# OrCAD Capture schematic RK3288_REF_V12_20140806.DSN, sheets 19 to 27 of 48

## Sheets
19 35.RAM-LPDDR2(220P) (option): size A3; title: RAM-LPDDR2(220P) (option); note: DDR-LPDDR2(220P) (option)
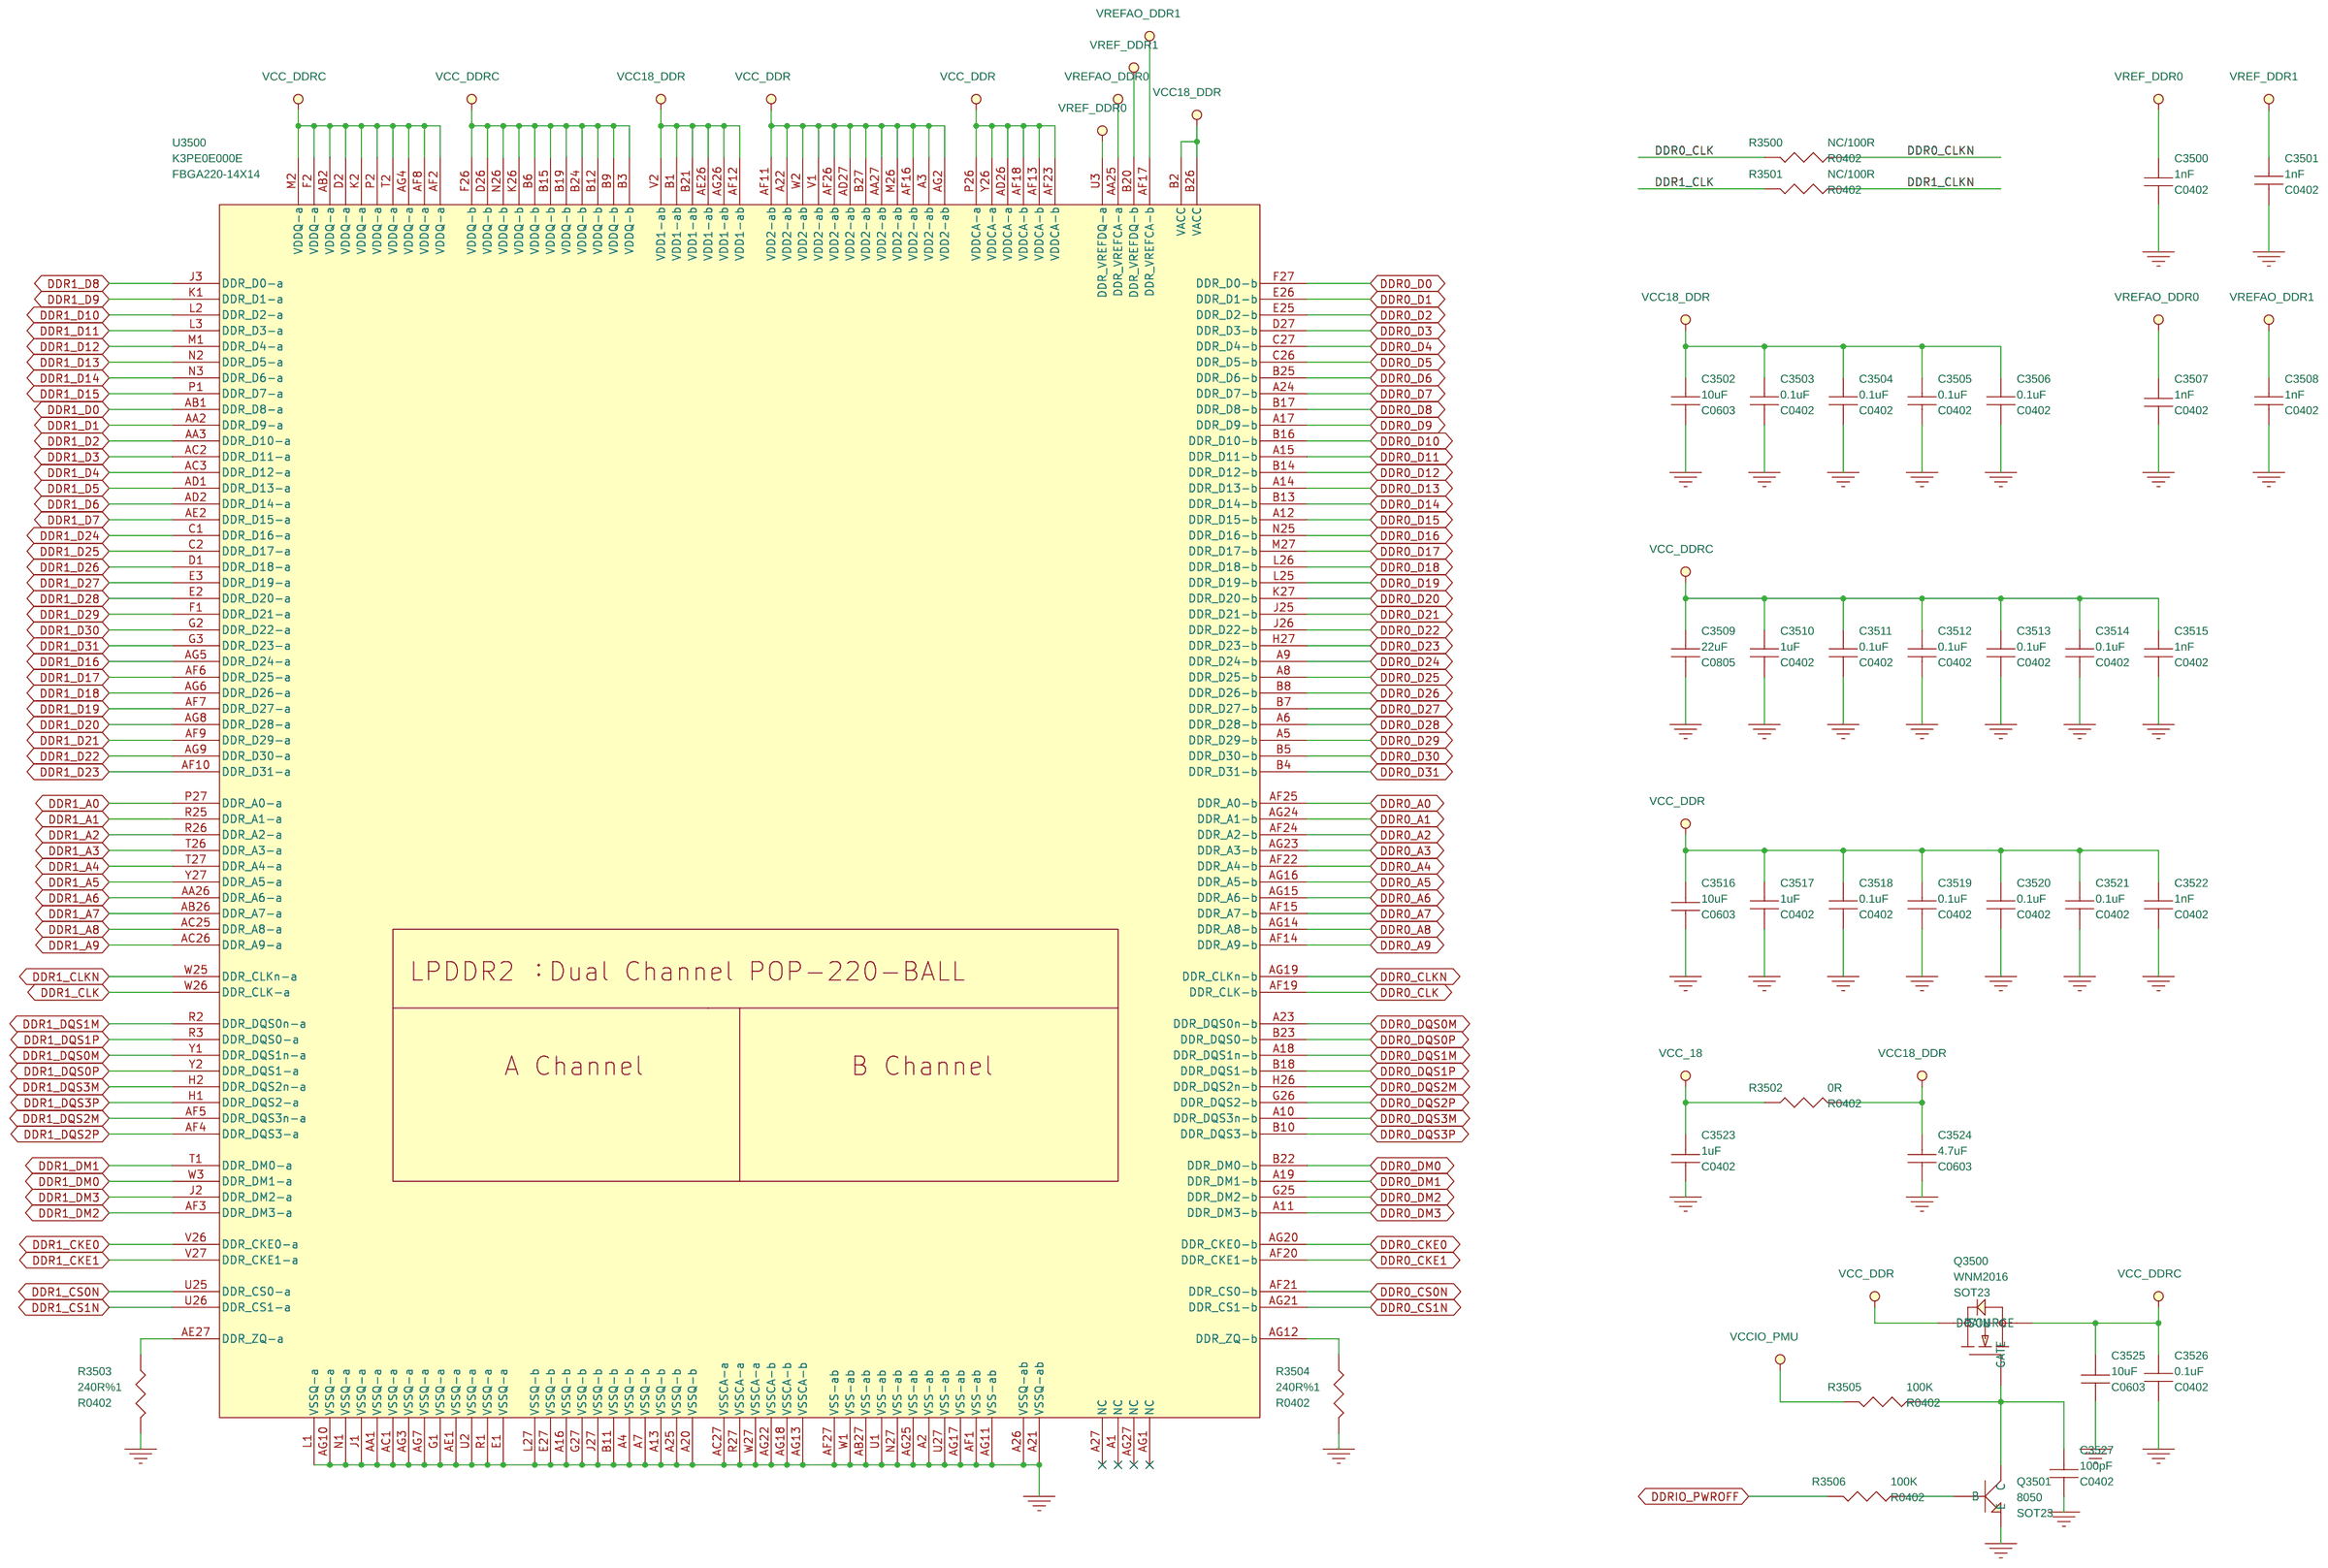
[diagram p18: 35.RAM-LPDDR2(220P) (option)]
20 36.RAM-LPDDR3(178P) (option): size Custom; title: RAM-LPDDR3(178P) (option); note: DDR-LPDDR3(178P) (option)
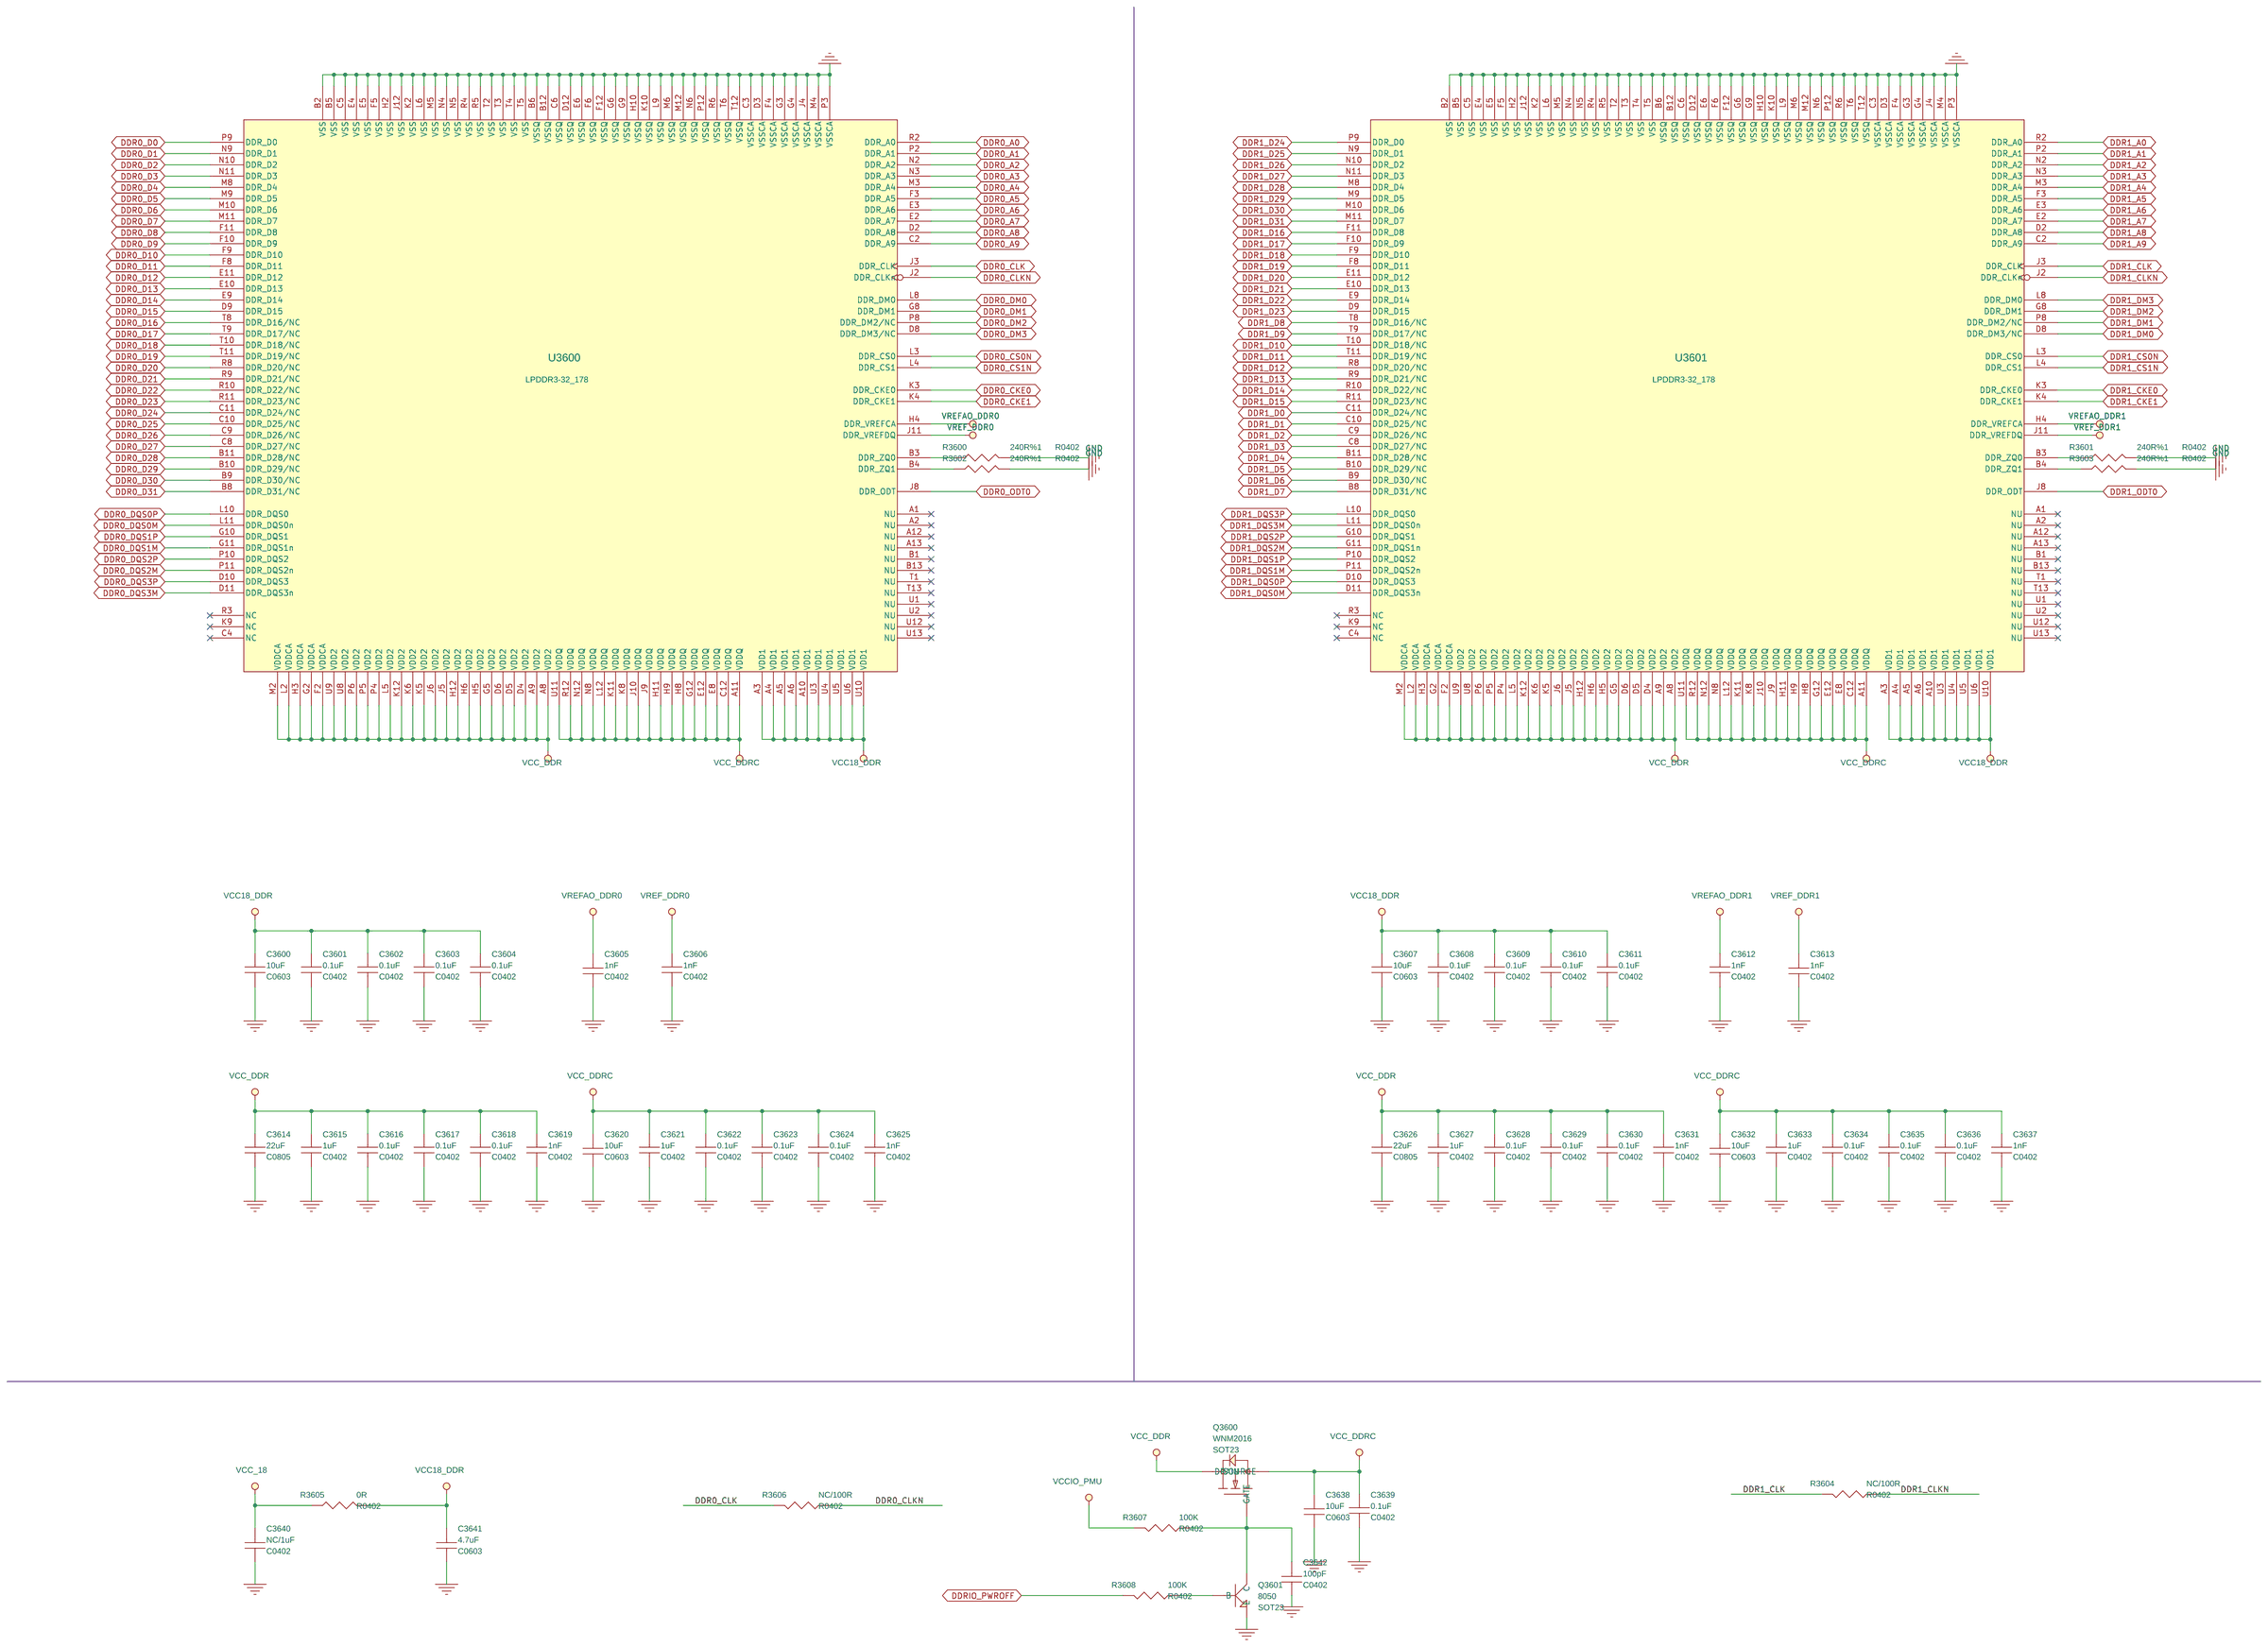
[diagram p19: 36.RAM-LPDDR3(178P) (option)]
21 40.Memory-eMMC: size A4; title: Flash-eMMC; note: Flash-eMMC
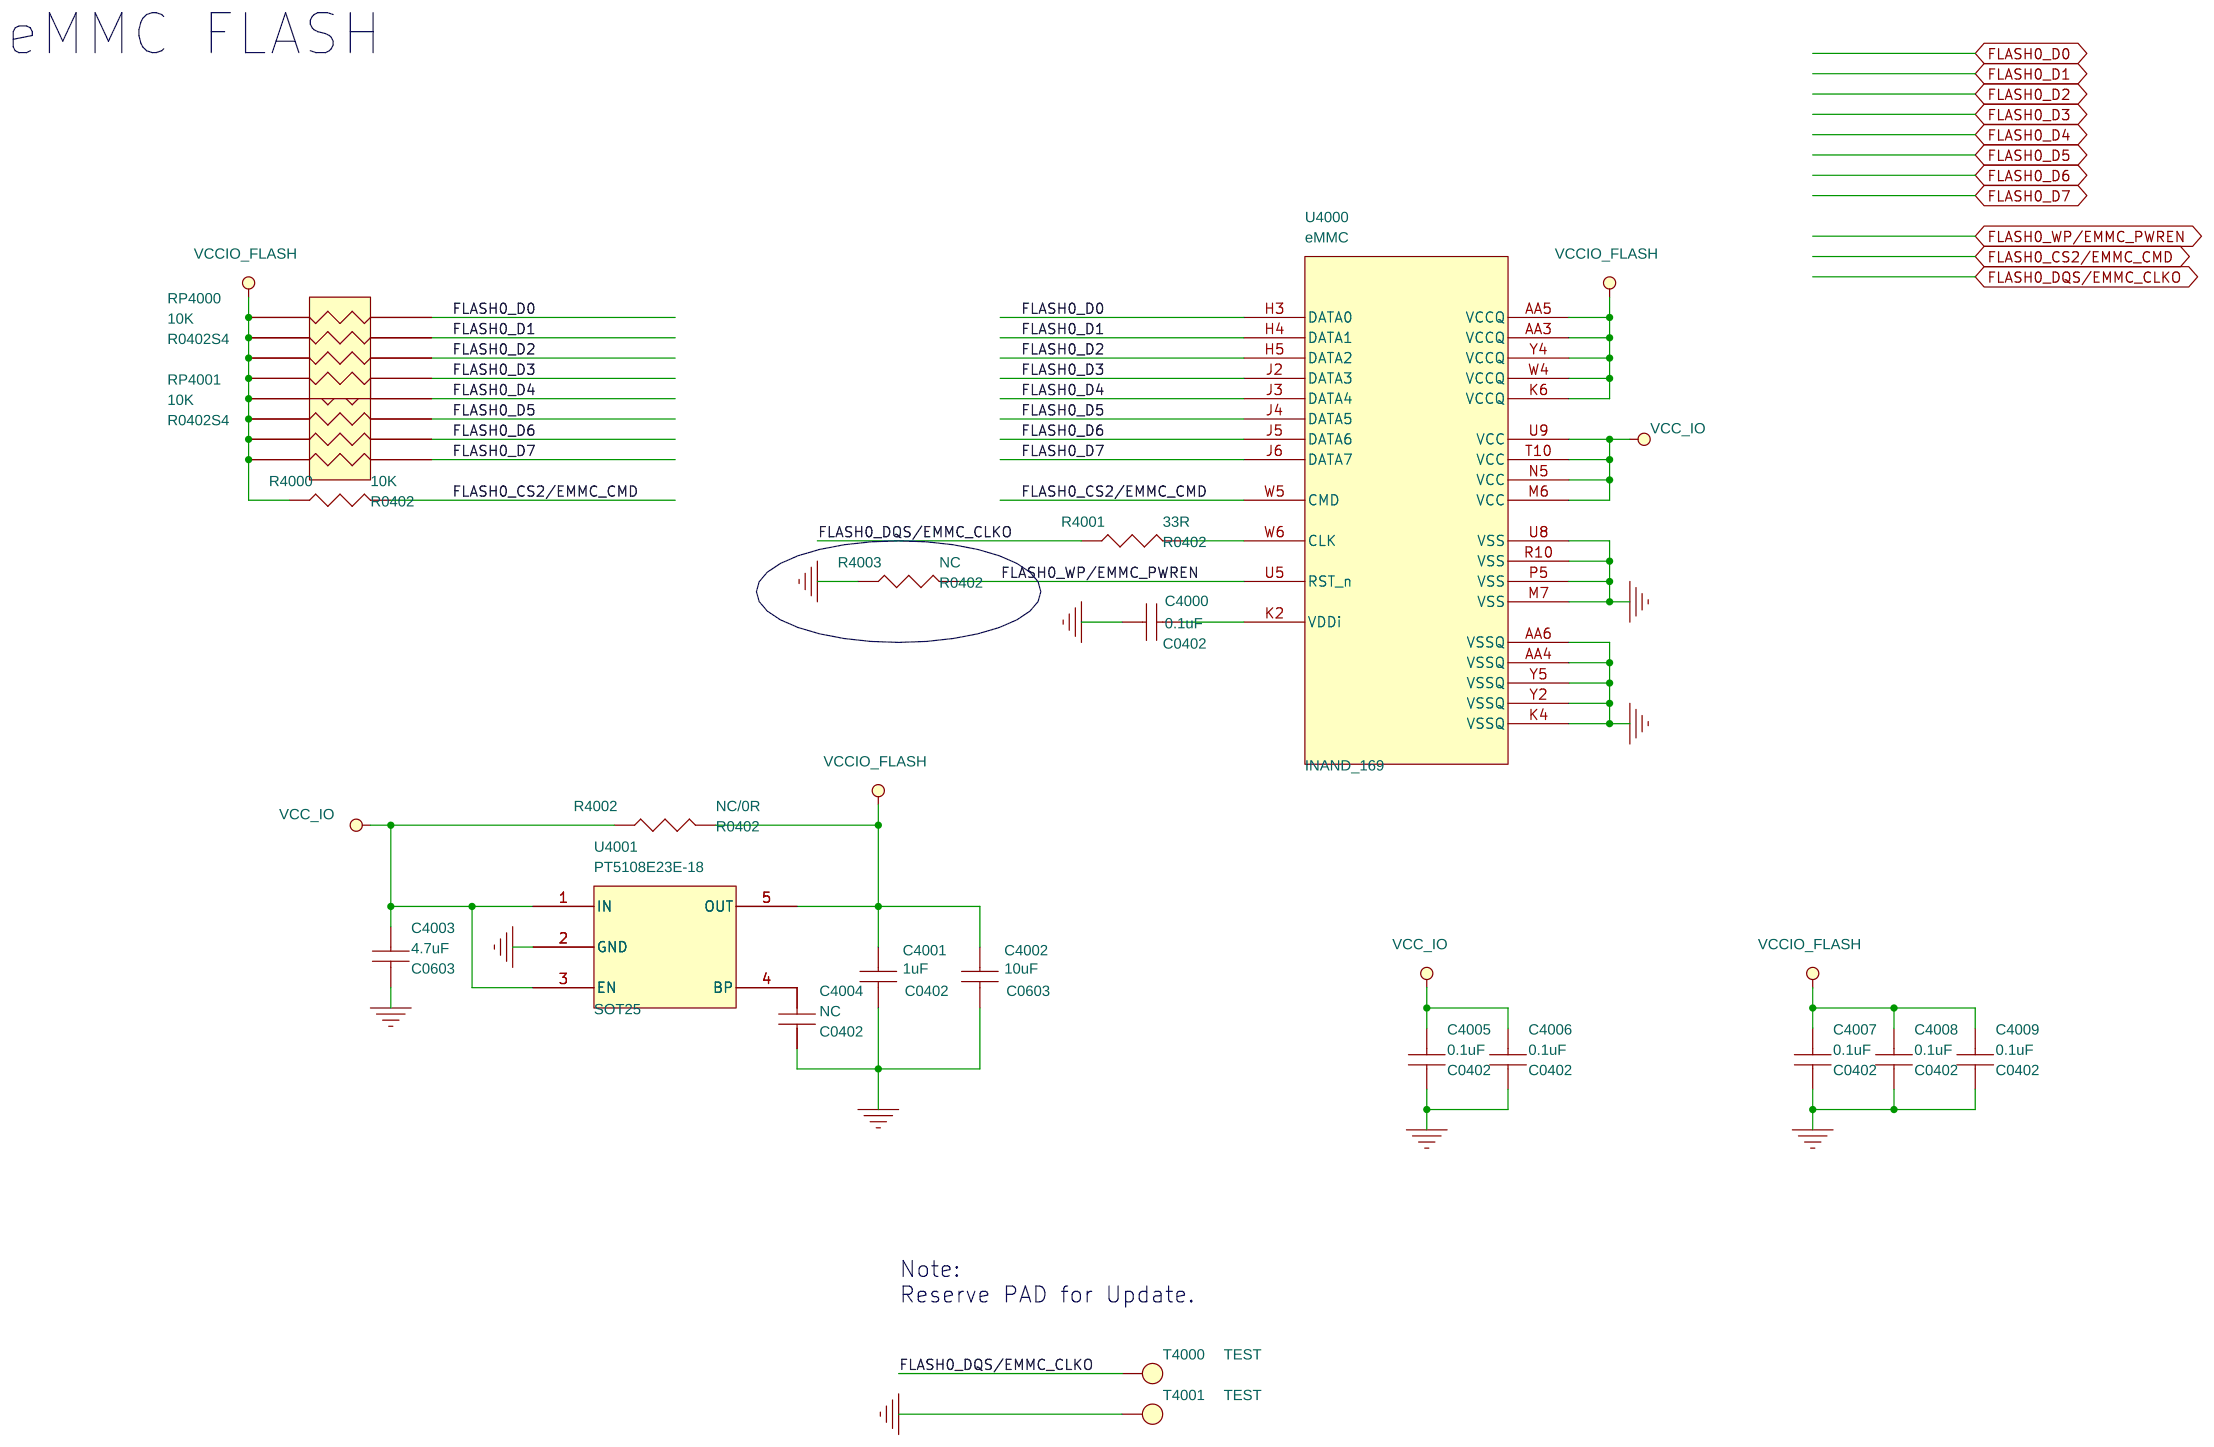
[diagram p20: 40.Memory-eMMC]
22 41.Memory-Nand FLASH (option): size A4; title: Flash-Nand FLASH (option); note: Flash-Nand FLASH (option)
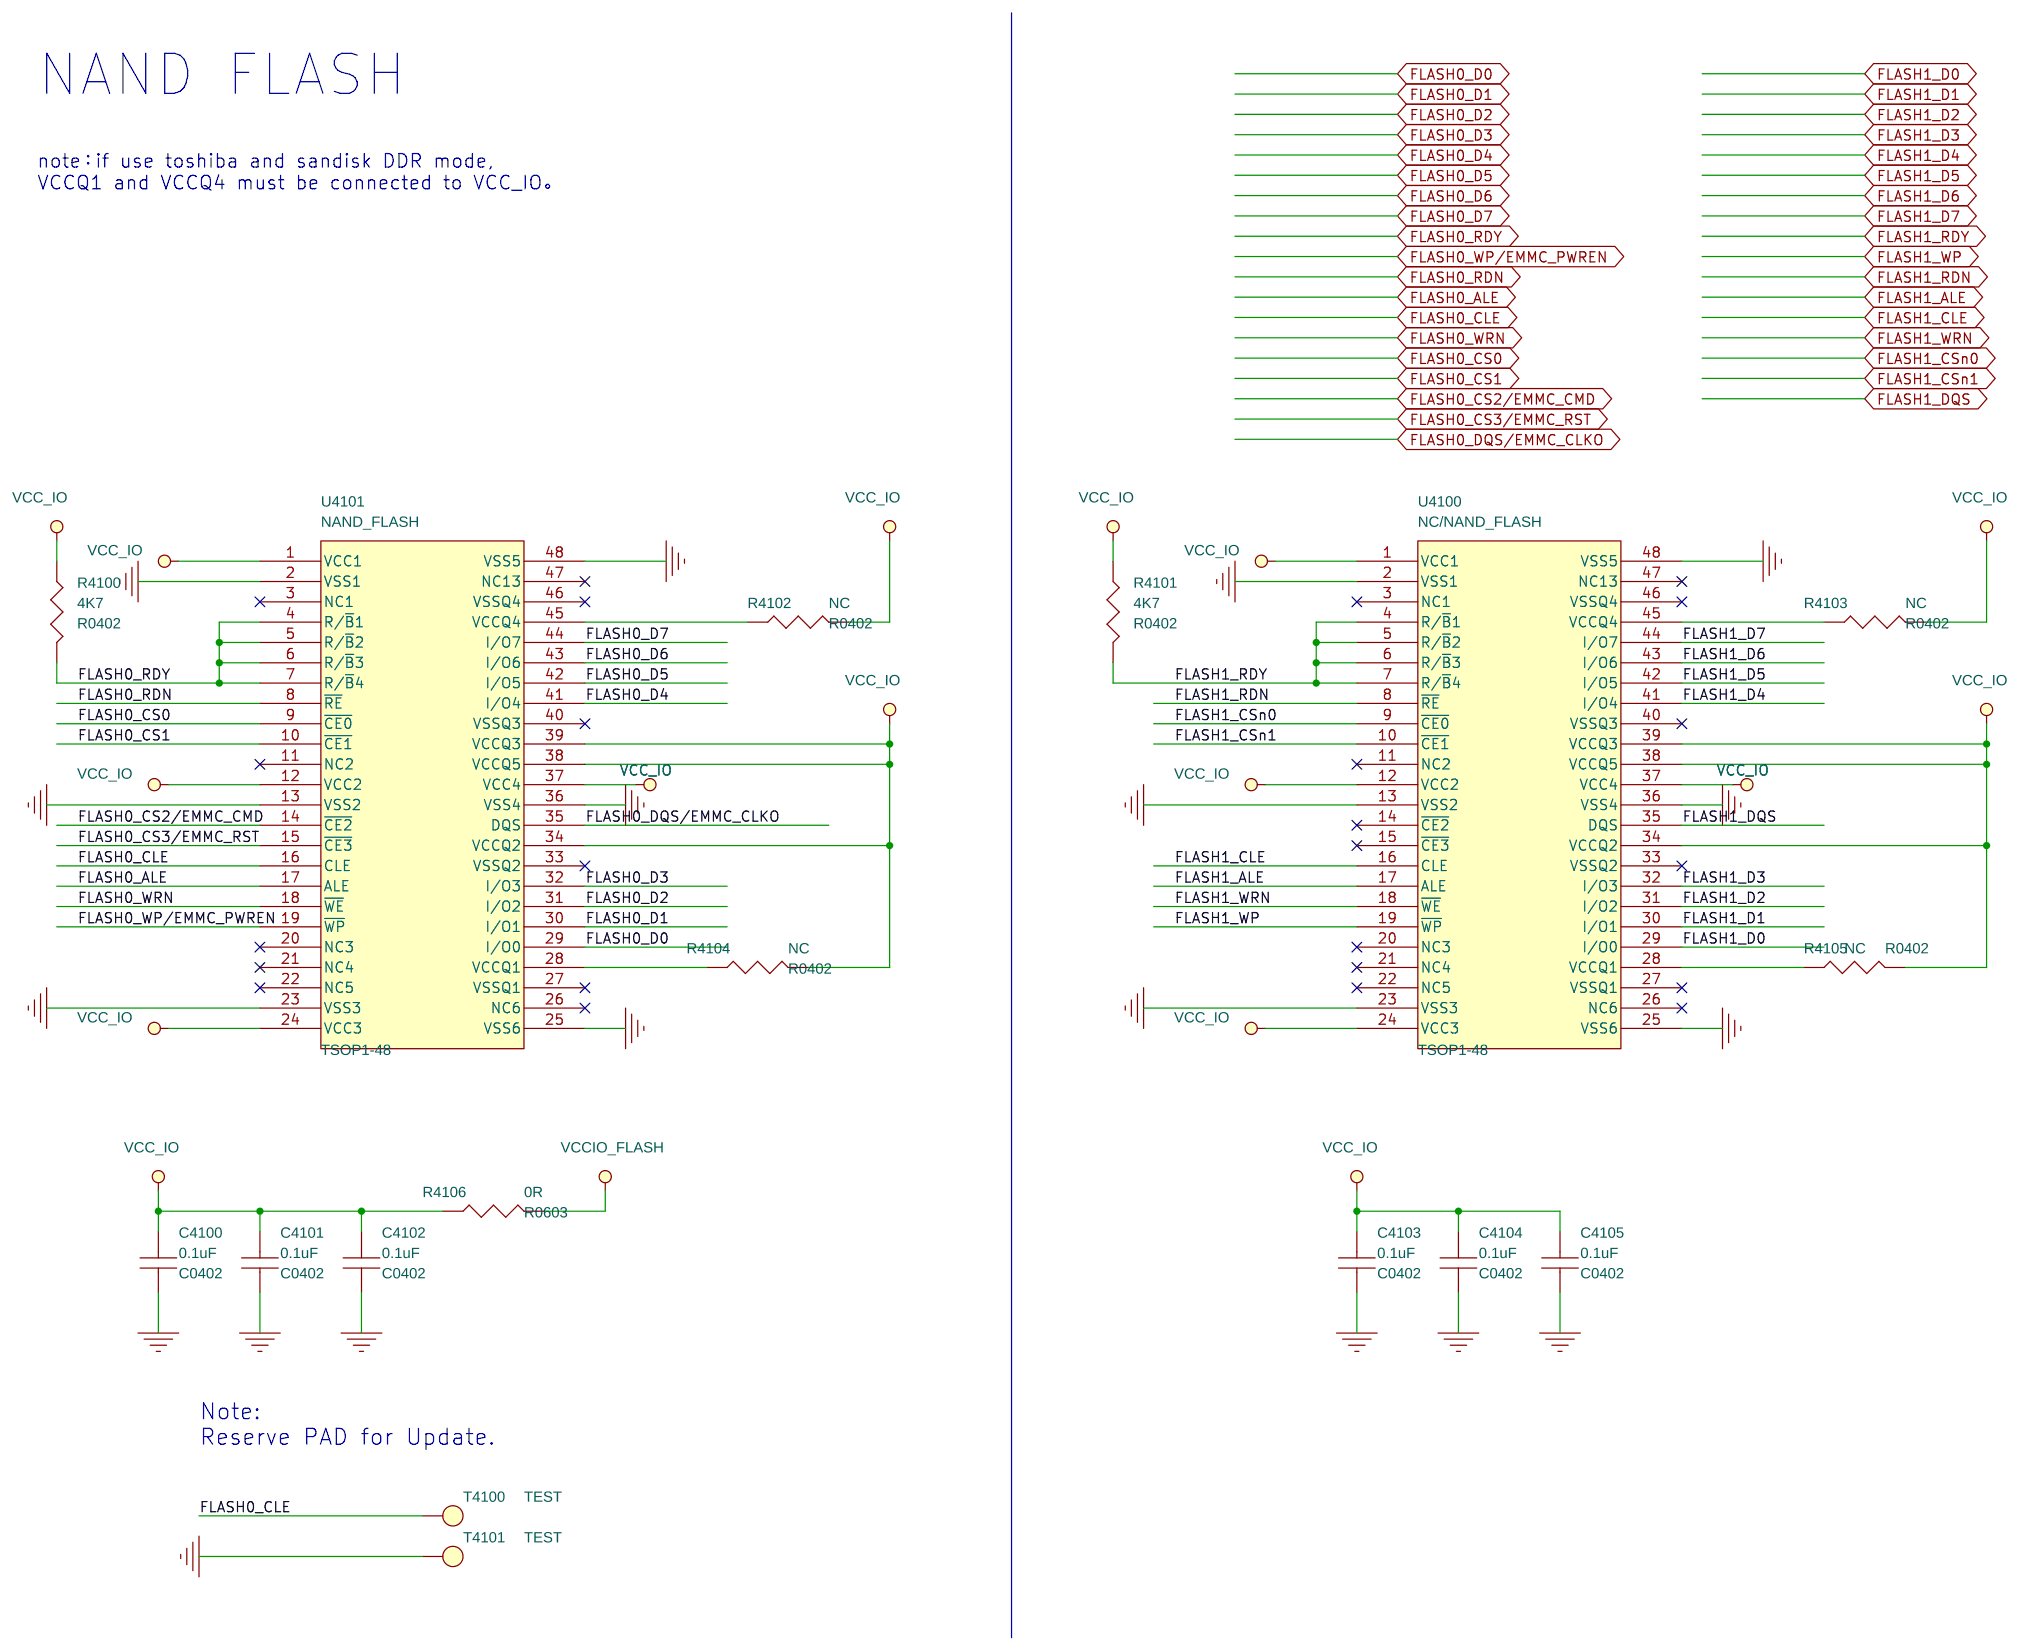
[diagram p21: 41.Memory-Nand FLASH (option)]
23 42.Memory-tSD (option): size A4; title: Flash-tSD (option); note: Flash-tSD (option)
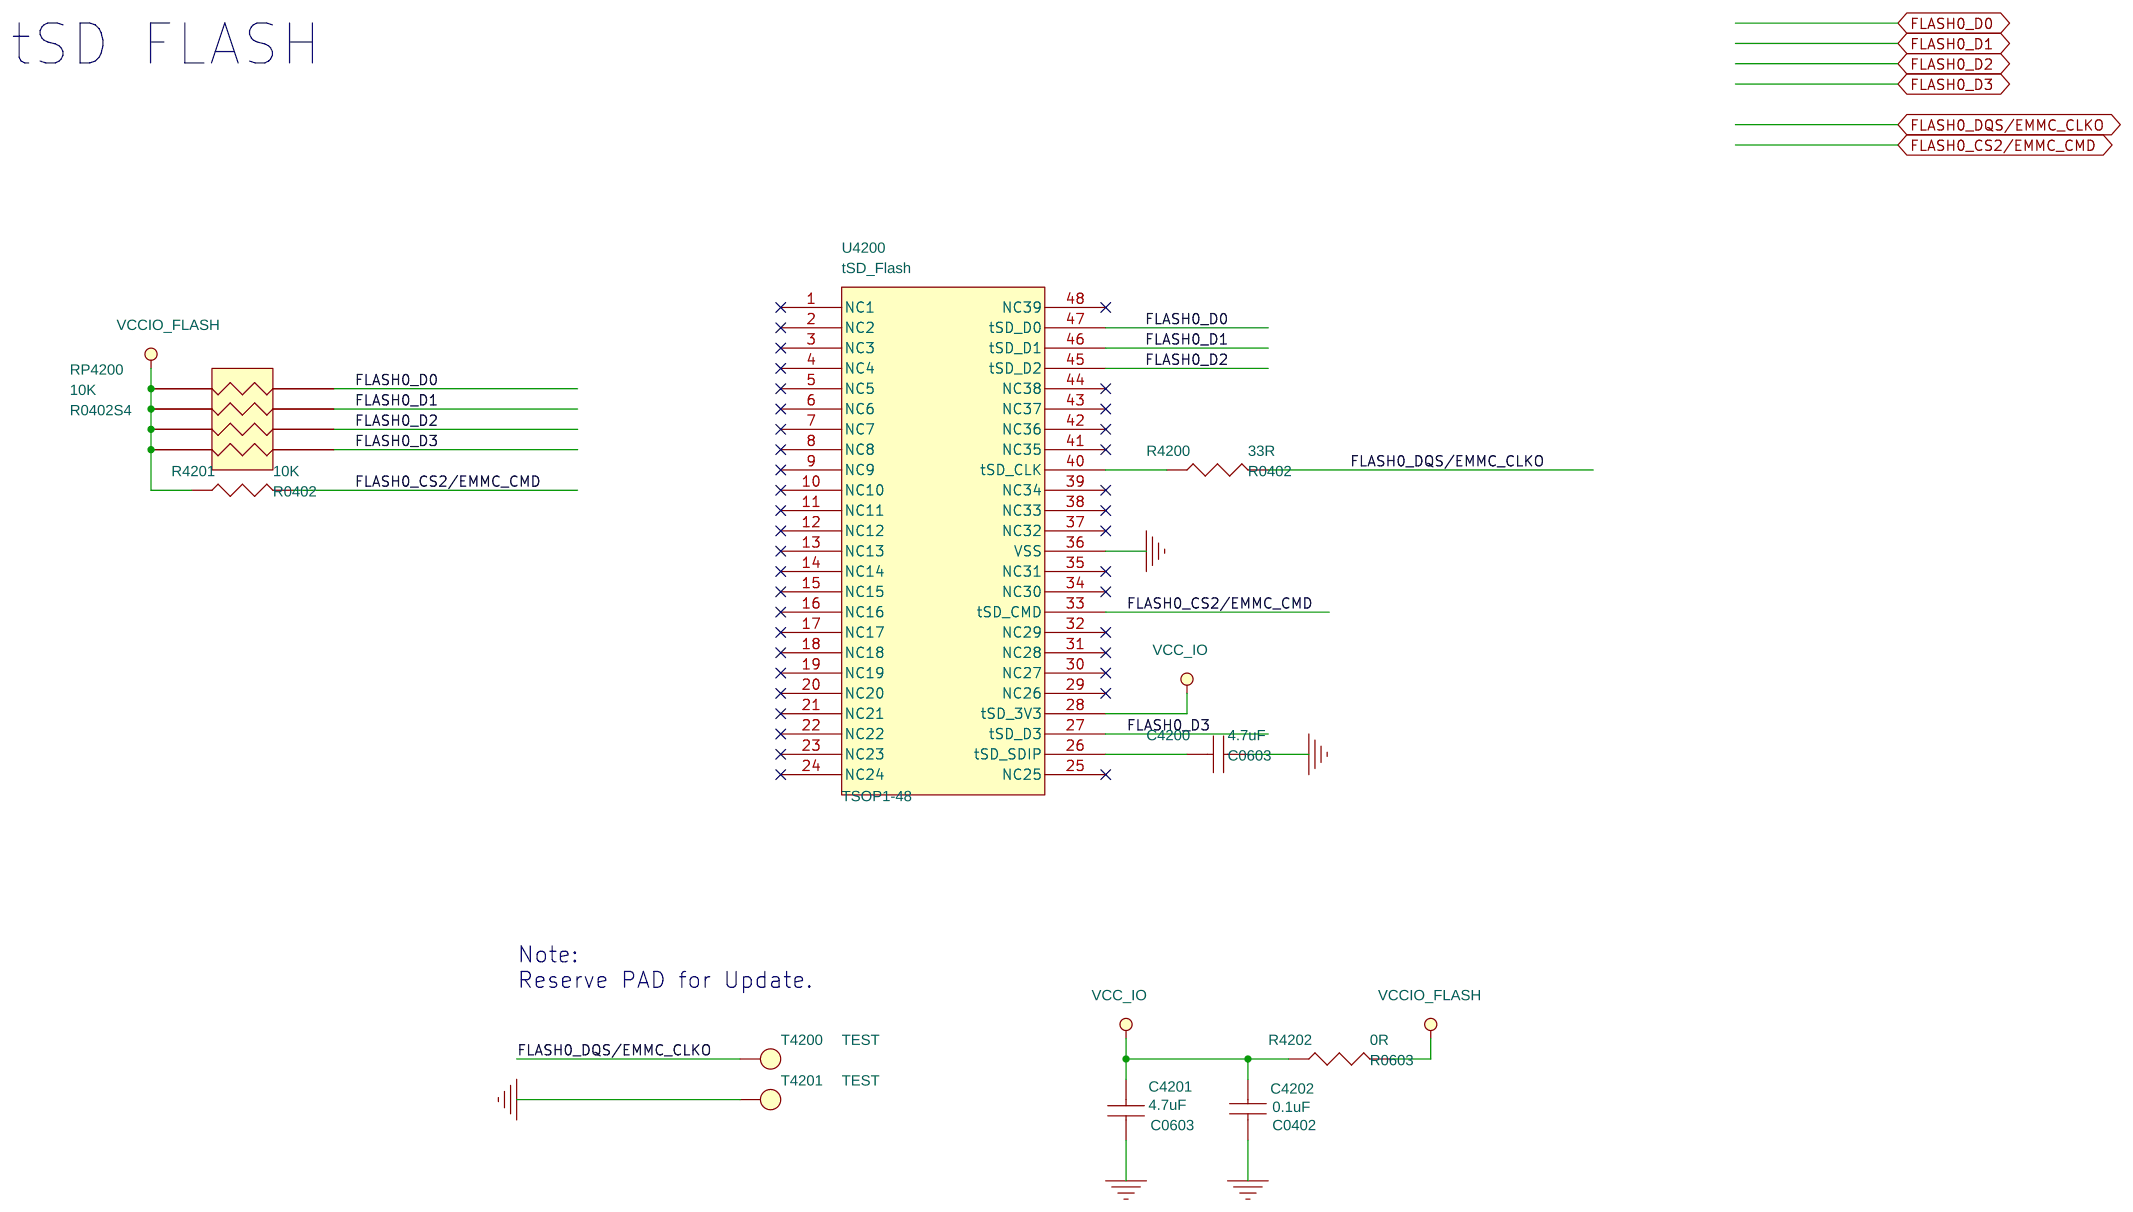
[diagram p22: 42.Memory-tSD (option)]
24 45.DVP power and Flash LED: size A3; title: DVP power and Flash LED; note: DVP power and Flash LED
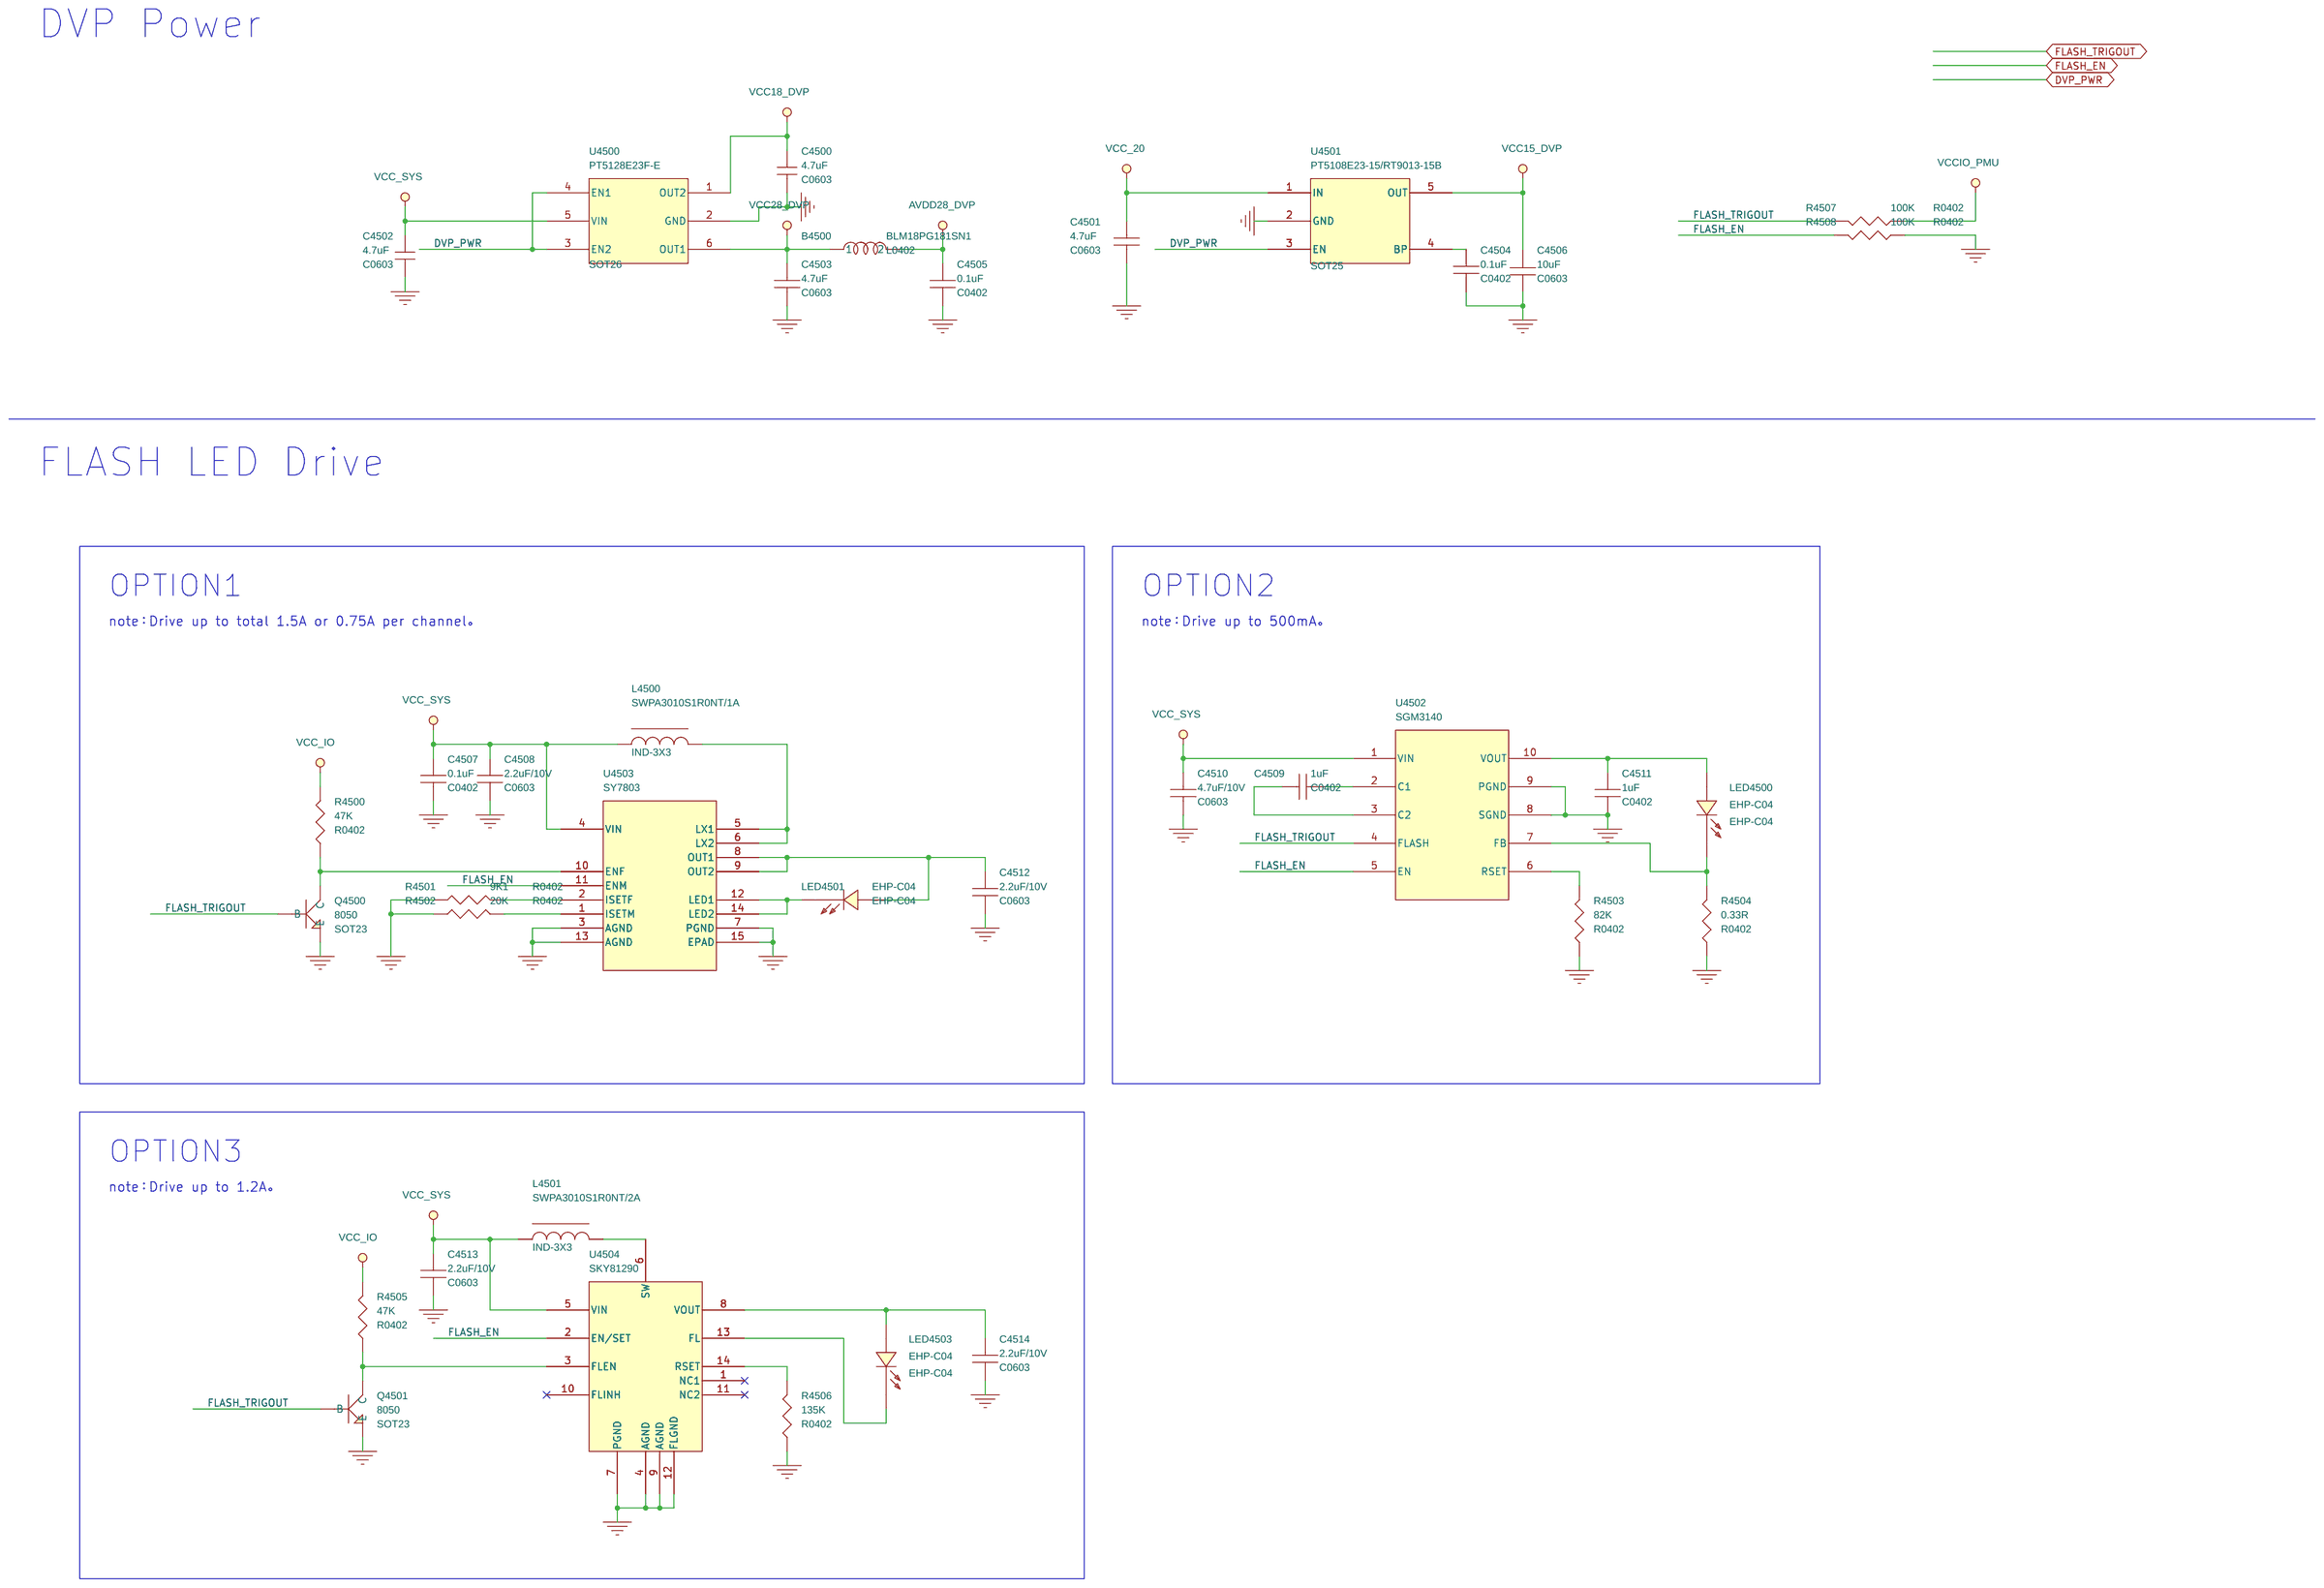
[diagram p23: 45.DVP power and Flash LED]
25 46.Camera-MIPI CSI: size A4; title: Camera-MIPI CSI; note: Camera-MIPI CSI
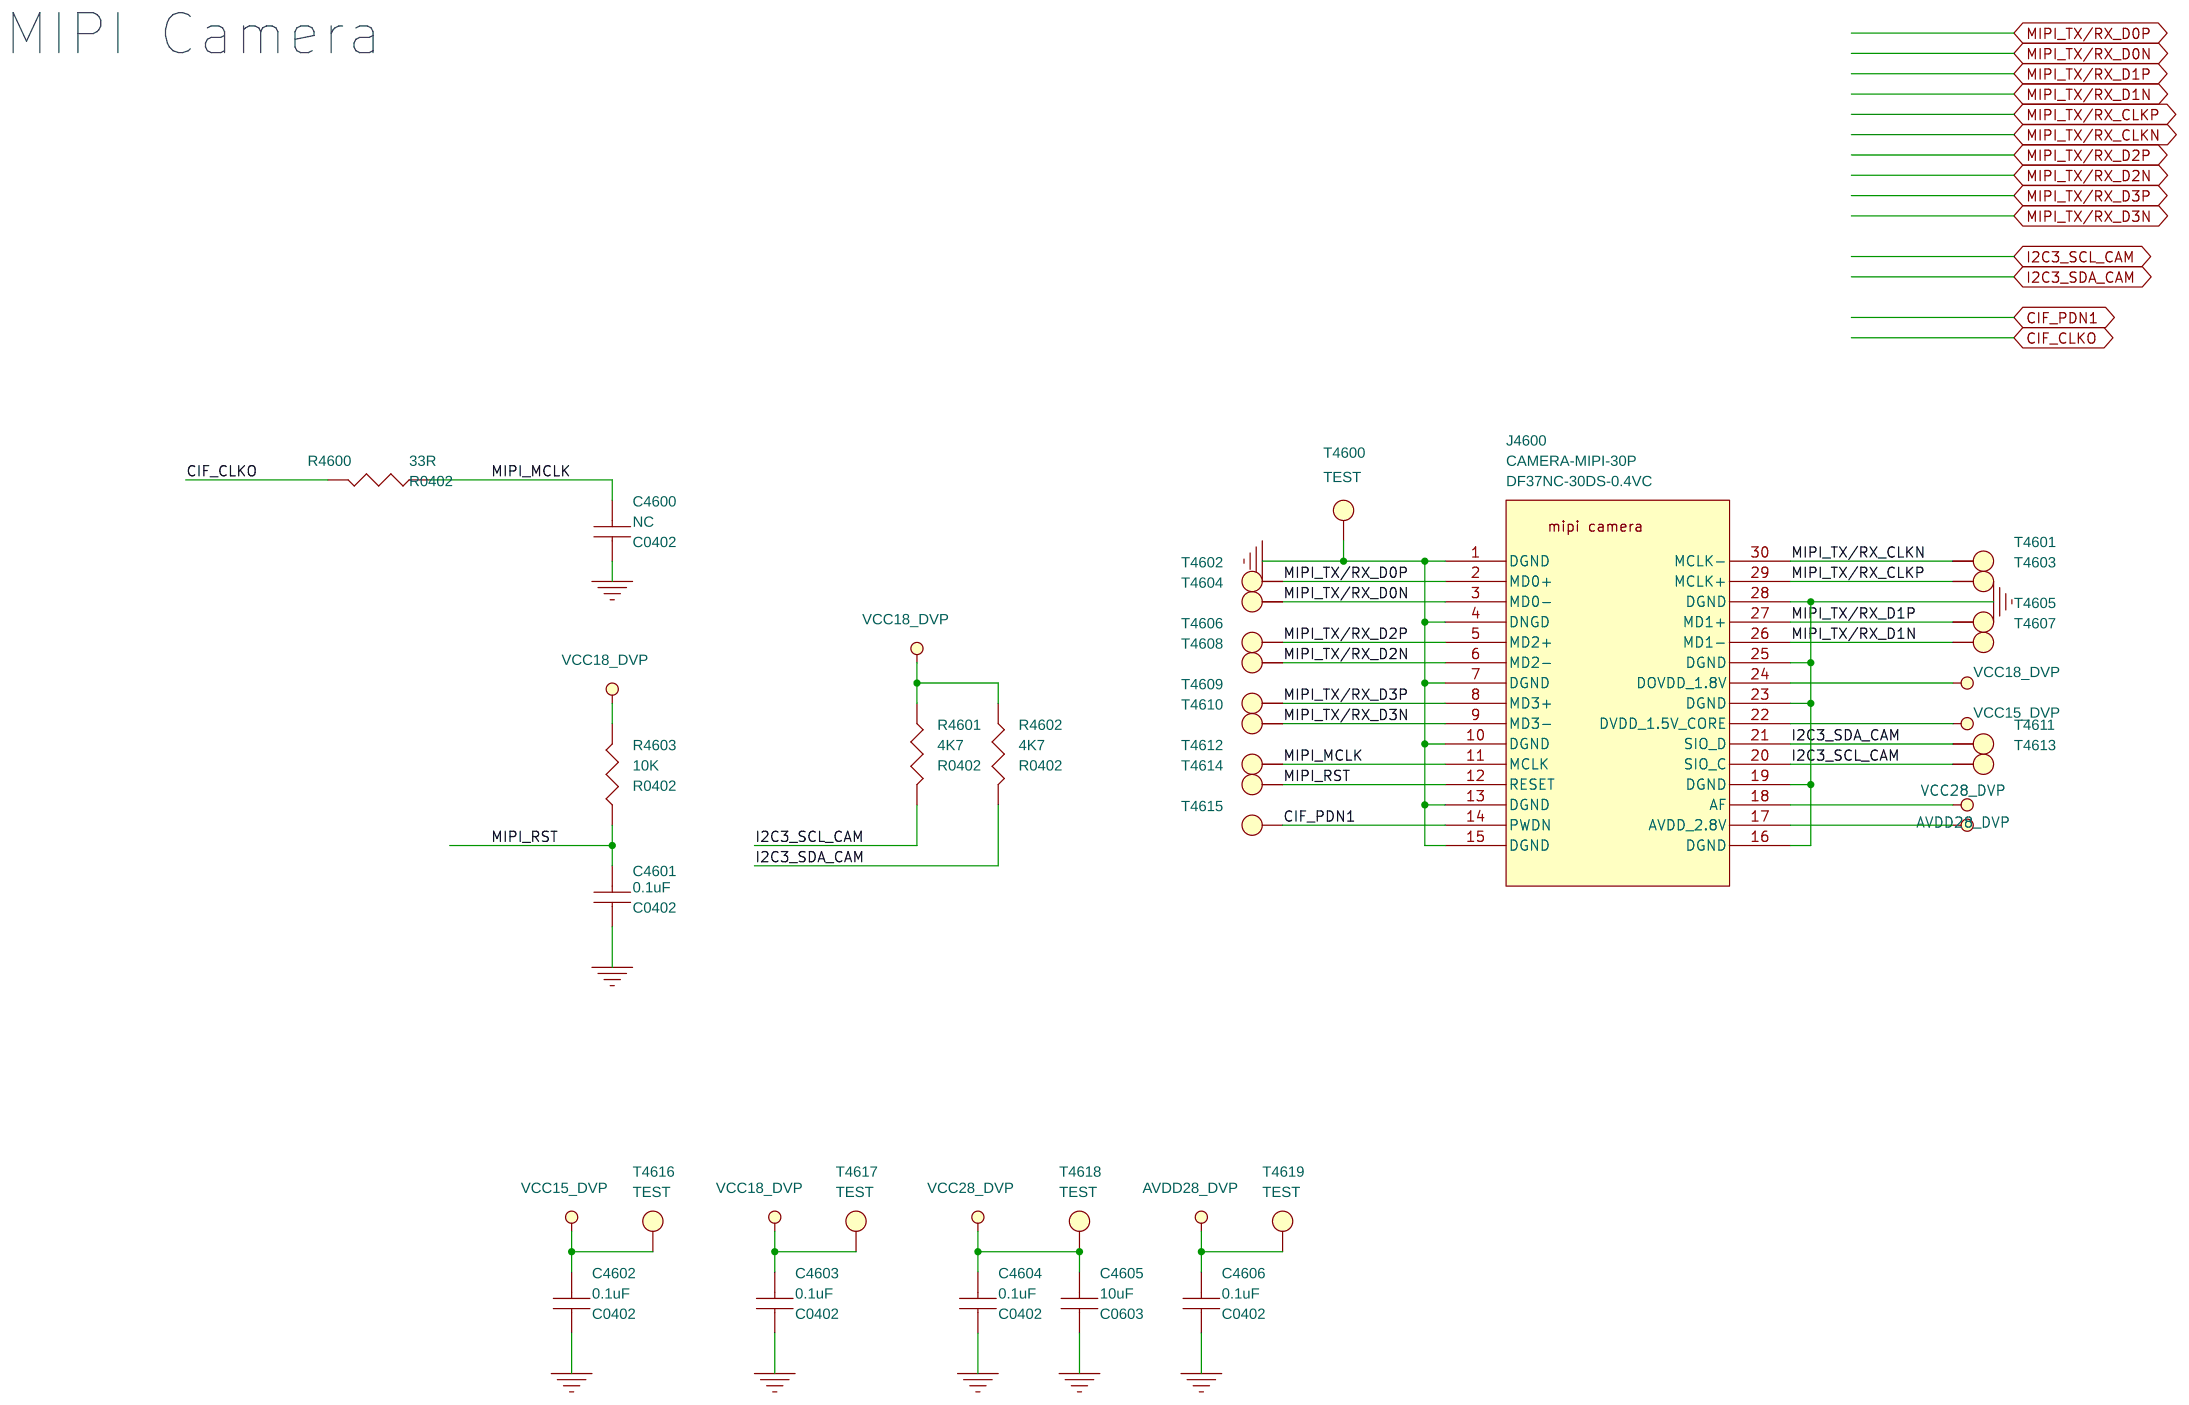
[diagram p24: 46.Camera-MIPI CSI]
26 47.Camera-CIF (option): size A4; title: Camera-CIF (option); note: Camera-CIF (option)
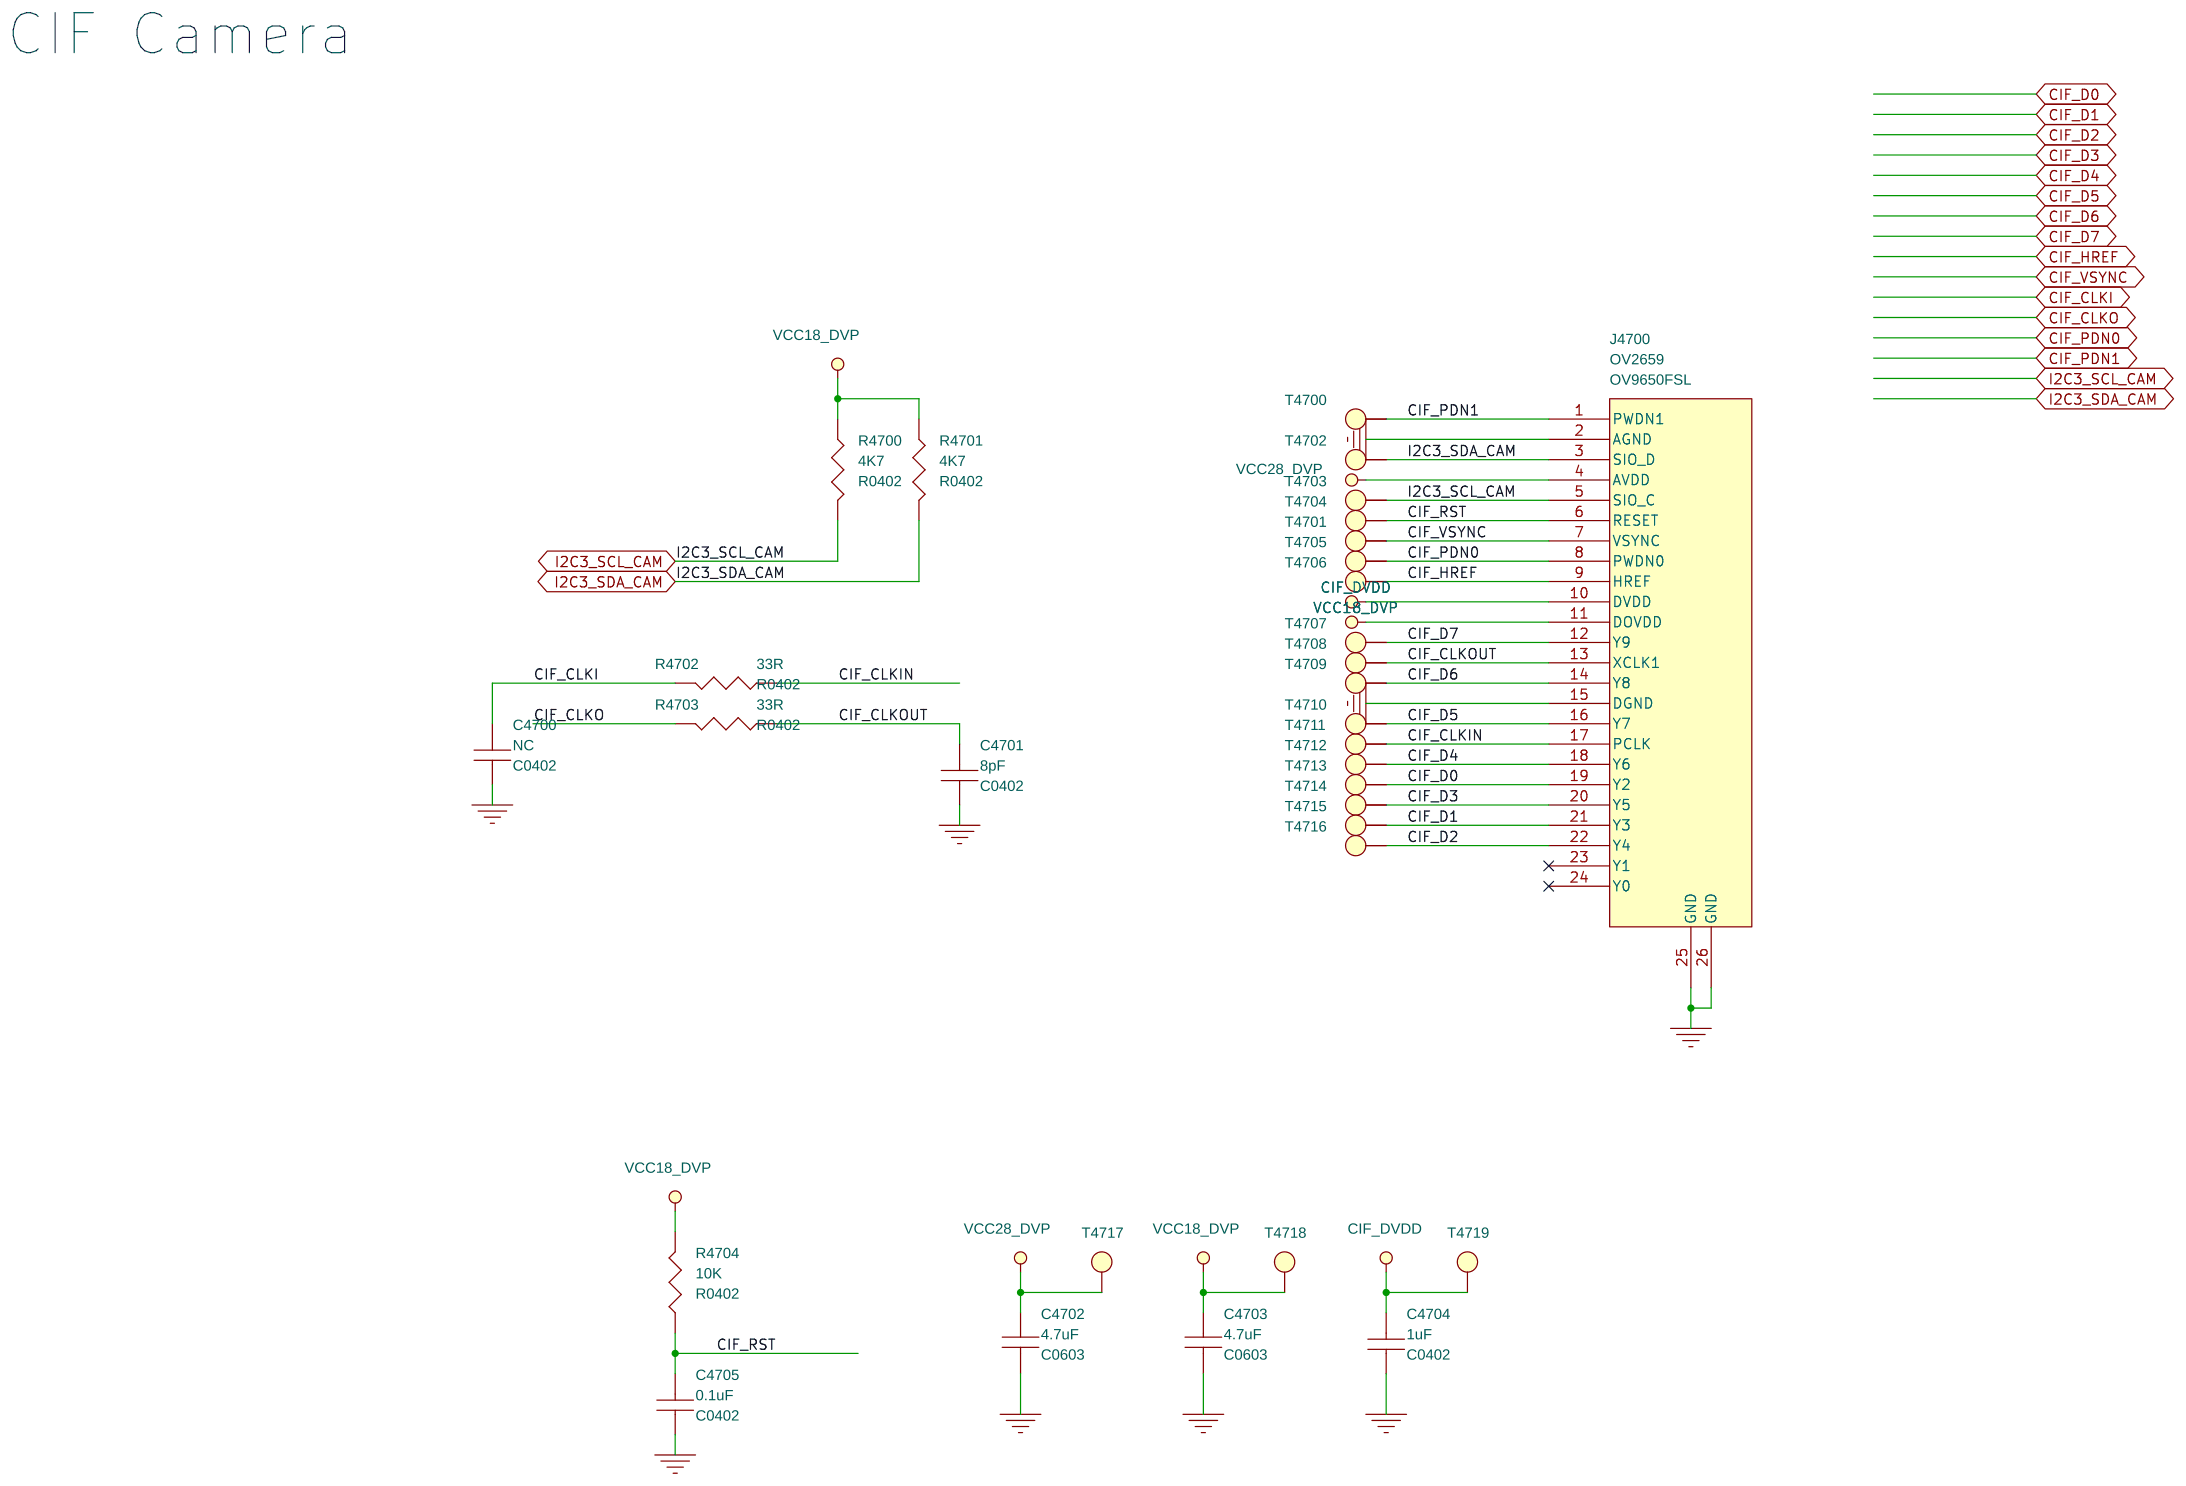
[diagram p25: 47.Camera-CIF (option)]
27 50.LCM-eDP Panel: size A4; title: LCM-eDP Panel; note: LCM-eDP Panel
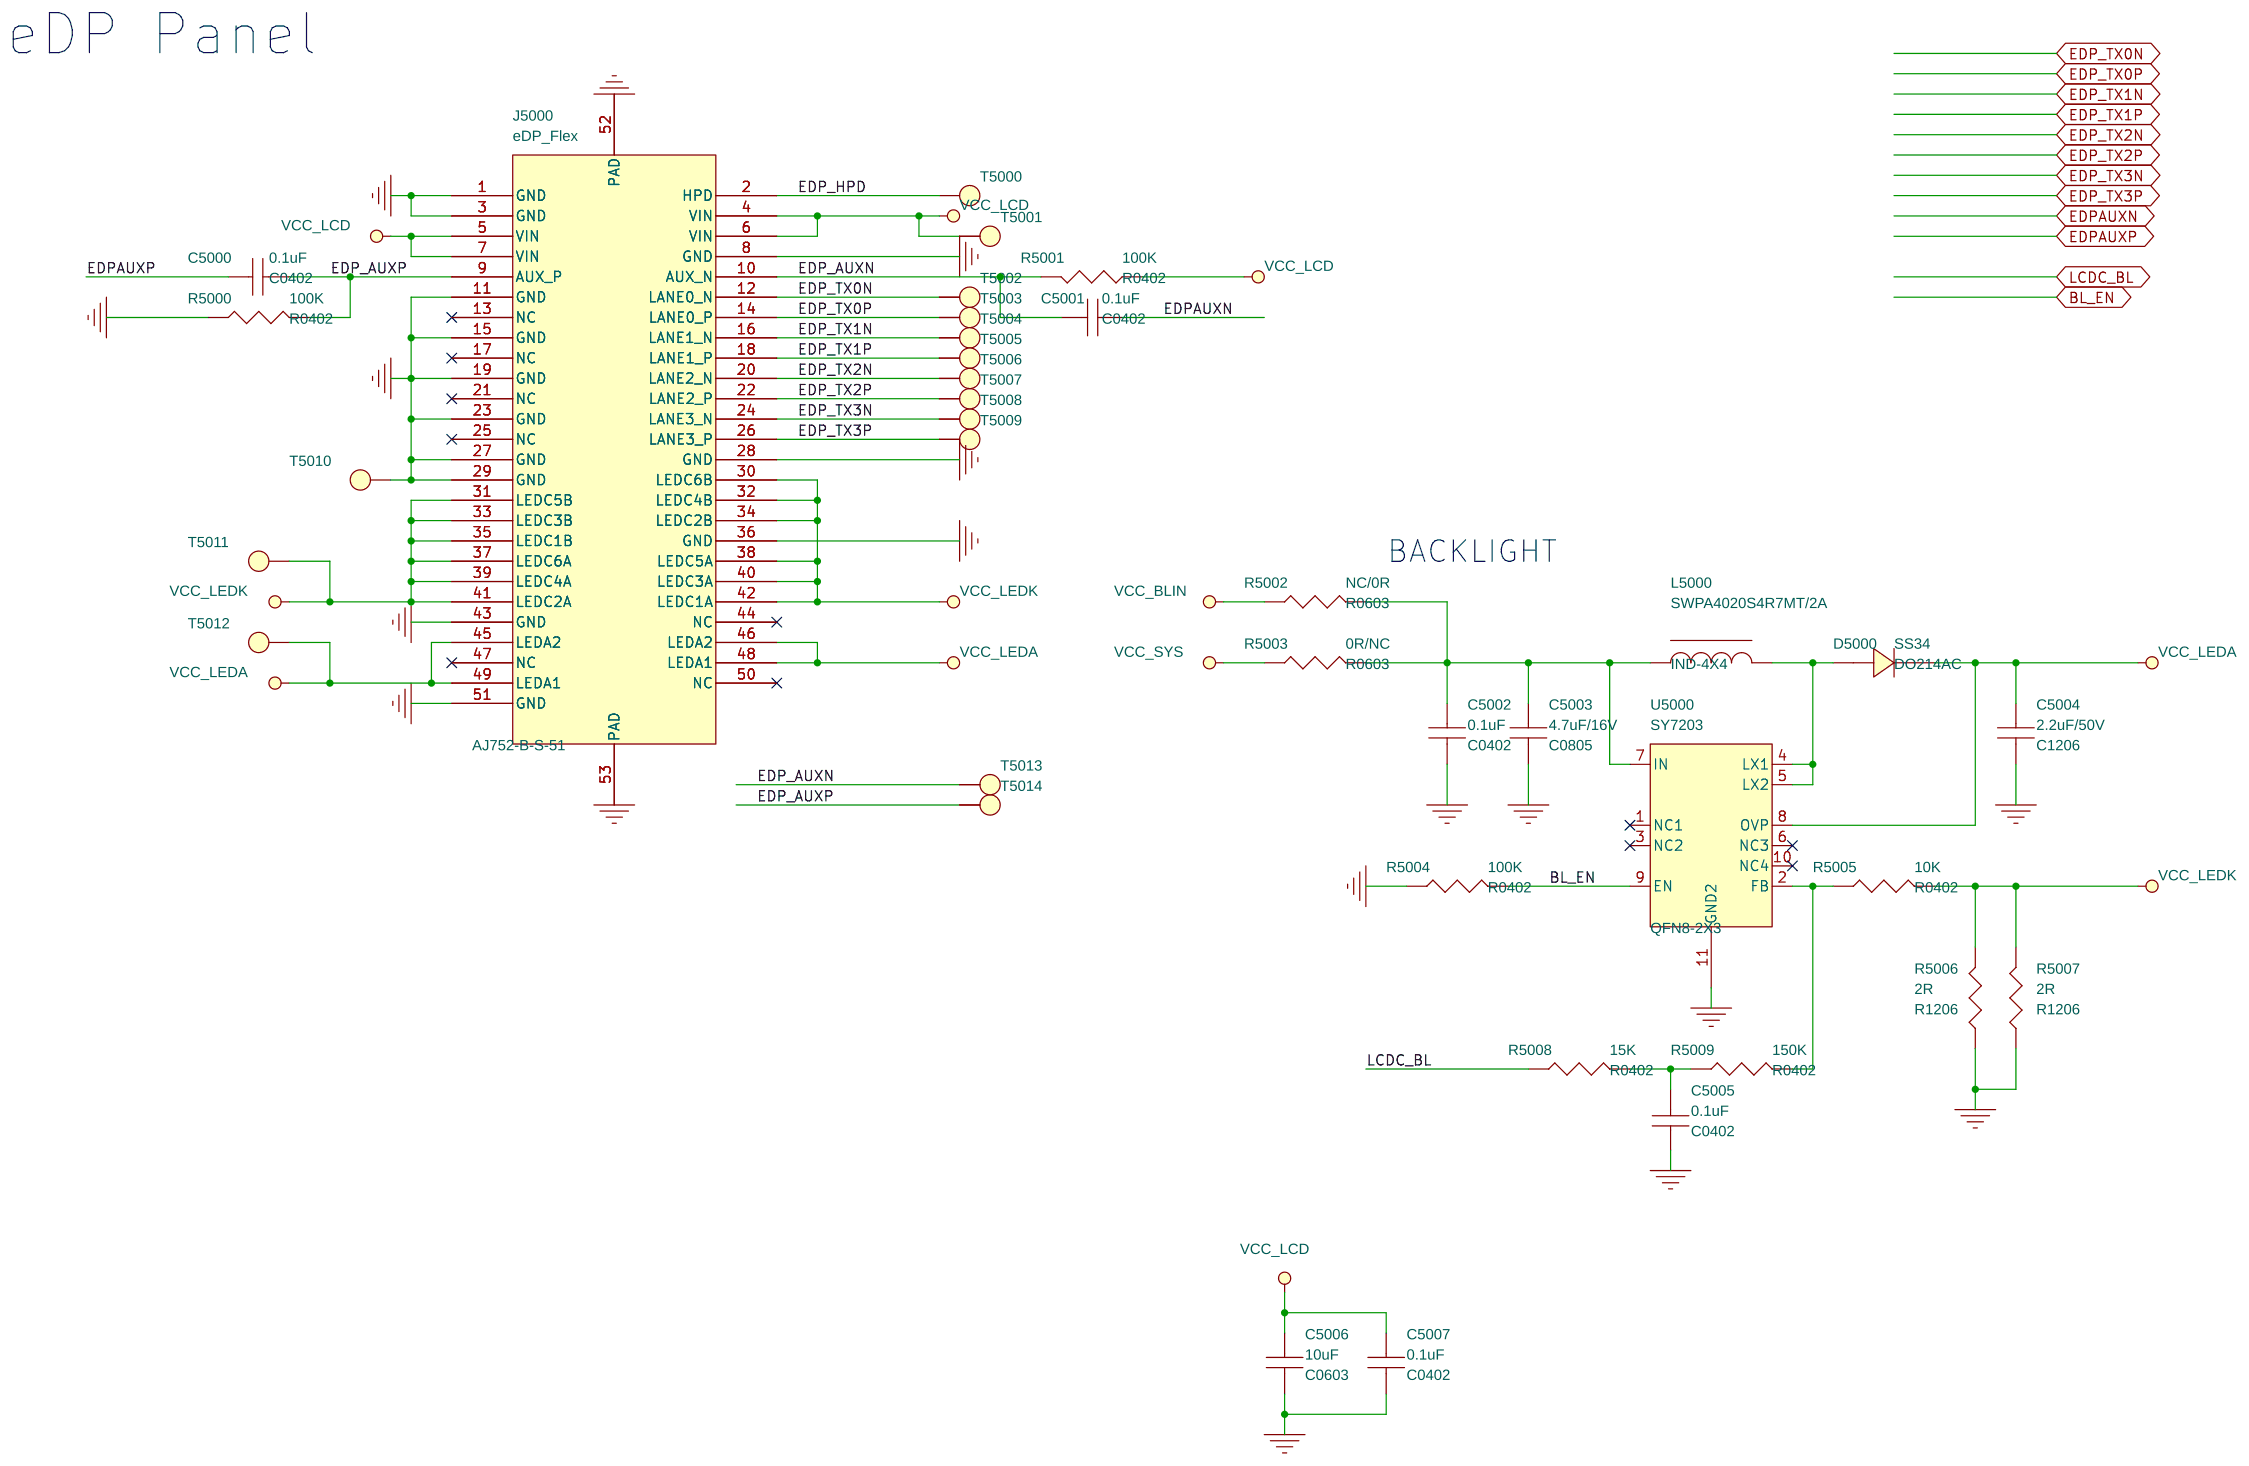
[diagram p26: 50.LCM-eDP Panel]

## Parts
sheet 35.RAM-LPDDR2(220P) (option)
C3500  1nF  [C0402]
C3501  1nF  [C0402]
C3502  10uF  [C0603]
C3503  0.1uF  [C0402]
C3504  0.1uF  [C0402]
C3505  0.1uF  [C0402]
C3506  0.1uF  [C0402]
C3507  1nF  [C0402]
C3508  1nF  [C0402]
C3509  22uF  [C0805]
C3510  1uF  [C0402]
C3511  0.1uF  [C0402]
C3512  0.1uF  [C0402]
C3513  0.1uF  [C0402]
C3514  0.1uF  [C0402]
C3515  1nF  [C0402]
C3516  10uF  [C0603]
C3517  1uF  [C0402]
C3518  0.1uF  [C0402]
C3519  0.1uF  [C0402]
C3520  0.1uF  [C0402]
C3521  0.1uF  [C0402]
C3522  1nF  [C0402]
C3523  1uF  [C0402]
C3524  4.7uF  [C0603]
C3525  10uF  [C0603]
C3526  0.1uF  [C0402]
C3527  100pF  [C0402]
Q3500  WNM2016  [SOT23]
Q3501  8050  [SOT23]
R3500  NC/100R  [R0402]
R3501  NC/100R  [R0402]
R3502  0R  [R0402]
R3503  240R%1  [R0402]
R3504  240R%1  [R0402]
R3505  100K  [R0402]
R3506  100K  [R0402]
U3500  K3PE0E000E  [FBGA220-14X14]
sheet 36.RAM-LPDDR3(178P) (option)
C3600  10uF  [C0603]
C3601  0.1uF  [C0402]
C3602  0.1uF  [C0402]
C3603  0.1uF  [C0402]
C3604  0.1uF  [C0402]
C3605  1nF  [C0402]
C3606  1nF  [C0402]
C3607  10uF  [C0603]
C3608  0.1uF  [C0402]
C3609  0.1uF  [C0402]
C3610  0.1uF  [C0402]
C3611  0.1uF  [C0402]
C3612  1nF  [C0402]
C3613  1nF  [C0402]
C3614  22uF  [C0805]
C3615  1uF  [C0402]
C3616  0.1uF  [C0402]
C3617  0.1uF  [C0402]
C3618  0.1uF  [C0402]
C3619  1nF  [C0402]
C3620  10uF  [C0603]
C3621  1uF  [C0402]
C3622  0.1uF  [C0402]
C3623  0.1uF  [C0402]
C3624  0.1uF  [C0402]
C3625  1nF  [C0402]
C3626  22uF  [C0805]
C3627  1uF  [C0402]
C3628  0.1uF  [C0402]
C3629  0.1uF  [C0402]
C3630  0.1uF  [C0402]
C3631  1nF  [C0402]
C3632  10uF  [C0603]
C3633  1uF  [C0402]
C3634  0.1uF  [C0402]
C3635  0.1uF  [C0402]
C3636  0.1uF  [C0402]
C3637  1nF  [C0402]
C3638  10uF  [C0603]
C3639  0.1uF  [C0402]
C3640  NC/1uF  [C0402]
C3641  4.7uF  [C0603]
C3642  100pF  [C0402]
Q3600  WNM2016  [SOT23]
Q3601  8050  [SOT23]
R3600  240R%1  [R0402]
R3601  240R%1  [R0402]
R3602  240R%1  [R0402]
R3603  240R%1  [R0402]
R3604  NC/100R  [R0402]
R3605  0R  [R0402]
R3606  NC/100R  [R0402]
R3607  100K  [R0402]
R3608  100K  [R0402]
U3600  LPDDR3-32_178  [FBGA178-13X11.5]
U3601  LPDDR3-32_178  [FBGA178-13X11.5]
sheet 40.Memory-eMMC
C4000  0.1uF  [C0402]
C4001  1uF  [C0402]
C4002  10uF  [C0603]
C4003  4.7uF  [C0603]
C4004  NC  [C0402]
C4005  0.1uF  [C0402]
C4006  0.1uF  [C0402]
C4007  0.1uF  [C0402]
C4008  0.1uF  [C0402]
C4009  0.1uF  [C0402]
R4000  10K  [R0402]
R4001  33R  [R0402]
R4002  NC/0R  [R0402]
R4003  NC  [R0402]
RP4000  10K  [R0402S4]
RP4001  10K  [R0402S4]
T4000  TEST  [T-0.7]
T4001  TEST  [T-0.7]
U4000  eMMC  [INAND_169]
U4001  PT5108E23E-18  [SOT25]
sheet 41.Memory-Nand FLASH (option)
C4100  0.1uF  [C0402]
C4101  0.1uF  [C0402]
C4102  0.1uF  [C0402]
C4103  0.1uF  [C0402]
C4104  0.1uF  [C0402]
C4105  0.1uF  [C0402]
R4100  4K7  [R0402]
R4101  4K7  [R0402]
R4102  NC  [R0402]
R4103  NC  [R0402]
R4104  NC  [R0402]
R4105  NC  [R0402]
R4106  0R  [R0603]
T4100  TEST  [T-0.7]
T4101  TEST  [T-0.7]
U4100  NC/NAND_FLASH  [TSOP1-48]
U4101  NAND_FLASH  [TSOP1-48]
sheet 42.Memory-tSD (option)
C4200  4.7uF  [C0603]
C4201  4.7uF  [C0603]
C4202  0.1uF  [C0402]
R4200  33R  [R0402]
R4201  10K  [R0402]
R4202  0R  [R0603]
RP4200  10K  [R0402S4]
T4200  TEST  [T-0.7]
T4201  TEST  [T-0.7]
U4200  tSD_Flash  [TSOP1-48]
sheet 45.DVP power and Flash LED
B4500  BLM18PG181SN1  [L0402]
C4500  4.7uF  [C0603]
C4501  4.7uF  [C0603]
C4502  4.7uF  [C0603]
C4503  4.7uF  [C0603]
C4504  0.1uF  [C0402]
C4505  0.1uF  [C0402]
C4506  10uF  [C0603]
C4507  0.1uF  [C0402]
C4508  2.2uF/10V  [C0603]
C4509  1uF  [C0402]
C4510  4.7uF/10V  [C0603]
C4511  1uF  [C0402]
C4512  2.2uF/10V  [C0603]
C4513  2.2uF/10V  [C0603]
C4514  2.2uF/10V  [C0603]
L4500  SWPA3010S1R0NT/1A  [IND-3X3]
L4501  SWPA3010S1R0NT/2A  [IND-3X3]
LED4500  EHP-C04  [EHP-C04]
LED4501  EHP-C04  [EHP-C04]
LED4503  EHP-C04  [EHP-C04]
Q4500  8050  [SOT23]
Q4501  8050  [SOT23]
R4500  47K  [R0402]
R4501  9K1  [R0402]
R4502  20K  [R0402]
R4503  82K  [R0402]
R4504  0.33R  [R0402]
R4505  47K  [R0402]
R4506  135K  [R0402]
R4507  100K  [R0402]
R4508  100K  [R0402]
U4500  PT5128E23F-E  [SOT26]
U4501  PT5108E23-15/RT9013-15B  [SOT25]
U4502  SGM3140  [DFN10-3X3]
U4503  SY7803  [QFN14-3X2]
U4504  SKY81290  [DFN14-2*3]
sheet 46.Camera-MIPI CSI
C4600  NC  [C0402]
C4601  0.1uF  [C0402]
C4602  0.1uF  [C0402]
C4603  0.1uF  [C0402]
C4604  0.1uF  [C0402]
C4605  10uF  [C0603]
C4606  0.1uF  [C0402]
J4600  CAMERA-MIPI-30P  [DF37NC-30DS-0.4VC]
R4600  33R  [R0402]
R4601  4K7  [R0402]
R4602  4K7  [R0402]
R4603  10K  [R0402]
T4600  TEST  [T-0.7]
T4601  TEST  [T-0.7]
T4602  TEST  [T-0.7]
T4603  TEST  [T-0.7]
T4604  TEST  [T-0.7]
T4605  TEST  [T-0.7]
T4606  TEST  [T-0.7]
T4607  TEST  [T-0.7]
T4608  TEST  [T-0.7]
T4609  TEST  [T-0.7]
T4610  TEST  [T-0.7]
T4611  TEST  [T-0.7]
T4612  TEST  [T-0.7]
T4613  TEST  [T-0.7]
T4614  TEST  [T-0.7]
T4615  TEST  [T-0.7]
T4616  TEST  [T-0.7]
T4617  TEST  [T-0.7]
T4618  TEST  [T-0.7]
T4619  TEST  [T-0.7]
sheet 47.Camera-CIF (option)
C4700  NC  [C0402]
C4701  8pF  [C0402]
C4702  4.7uF  [C0603]
C4703  4.7uF  [C0603]
C4704  1uF  [C0402]
C4705  0.1uF  [C0402]
J4700  OV2659  [OV9650FSL]
R4700  4K7  [R0402]
R4701  4K7  [R0402]
R4702  33R  [R0402]
R4703  33R  [R0402]
R4704  10K  [R0402]
T4700  TEST  [T-0.7]
T4701  TEST  [T-0.7]
T4702  TEST  [T-0.7]
T4703  TEST  [T-0.7]
T4704  TEST  [T-0.7]
T4705  TEST  [T-0.7]
T4706  TEST  [T-0.7]
T4707  TEST  [T-0.7]
T4708  TEST  [T-0.7]
T4709  TEST  [T-0.7]
T4710  TEST  [T-0.7]
T4711  TEST  [T-0.7]
T4712  TEST  [T-0.7]
T4713  TEST  [T-0.7]
T4714  TEST  [T-0.7]
T4715  TEST  [T-0.7]
T4716  TEST  [T-0.7]
T4717  TEST  [T-0.7]
T4718  TEST  [T-0.7]
T4719  TEST  [T-0.7]
sheet 50.LCM-eDP Panel
C5000  0.1uF  [C0402]
C5001  0.1uF  [C0402]
C5002  0.1uF  [C0402]
C5003  4.7uF/16V  [C0805]
C5004  2.2uF/50V  [C1206]
C5005  0.1uF  [C0402]
C5006  10uF  [C0603]
C5007  0.1uF  [C0402]
D5000  SS34  [DO214AC]
J5000  eDP_Flex  [AJ752-B-S-51]
L5000  SWPA4020S4R7MT/2A  [IND-4X4]
R5000  100K  [R0402]
R5001  100K  [R0402]
R5002  NC/0R  [R0603]
R5003  0R/NC  [R0603]
R5004  100K  [R0402]
R5005  10K  [R0402]
R5006  2R  [R1206]
R5007  2R  [R1206]
R5008  15K  [R0402]
R5009  150K  [R0402]
T5000  TEST  [T-0.7]
T5001  TEST  [T-0.7]
T5002  TEST  [T-0.7]
T5003  TEST  [T-0.7]
T5004  TEST  [T-0.7]
T5005  TEST  [T-0.7]
T5006  TEST  [T-0.7]
T5007  TEST  [T-0.7]
T5008  TEST  [T-0.7]
T5009  TEST  [T-0.7]
T5010  TEST  [T-0.7]
T5011  TEST  [T-0.7]
T5012  TEST  [T-0.7]
T5013  TEST  [T-0.7]
T5014  TEST  [T-0.7]
U5000  SY7203  [QFN8-2X3]

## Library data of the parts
C3500-C3522 C3525-C3527 C3600-C3639 C3642 C4501 C4504 C4506 C5003 = CAP_NP
C3523 C3524 C3640 C3641 = CAP_NP: CAP,MLCC,10uF,+/-10%,X5R,6.3V,SMD0805
Q3500 Q3600 = FET_N_MOS
Q3501 Q3601 Q4500 Q4501 = NPN4
R3500-R3504 R3600-R3606 = RESISTOR_0: 贴片电阻
R3505 R3506 R3607 R3608 = RESISTOR_0: RES,thick film,1MOhm,+/-5%,1/16W,SMD0402; MARK: 51K
U3500 = K3PE0E000E_0
U3600 U3601 = LPDDR3-32bit-178PIN
C4000 C4004-C4009 C4100-C4105 C4202 C5005 = CAP_NP: RoHS CHIP CAP 0.1uF +10/-10% X7R
C4001-C4003 = CAP_NP: RoHS CHIP CAP 4.7uF +10/-10% X5R
R4000 R4201 = RESISTOR: ROHS CHIP RES 10K 1/16W +/-5%
R4001 R4200 R4603 R4704 = RESISTOR: NC
R4002 = RESISTOR: ROHS CHIP RES 10K 1/16W 5%
R4003 R4102-R4105 = RESISTOR
RP4000 RP4001 RP4200 = RESISTOR_4PACK: ROHS CHIP RES 10K 1/16W +/-5%
T4000 T4001 T4100 T4101 T4200 T4201 = TESTPOINT1: test
U4000 = INAND: NAND Flash,H26M54001BKR,2.7V,3.3V,3.6V,128G,N/A,-25℃~85℃,FBGA-169P
U4001 U4501 = LDO-PT5108_RT9013
R4100 R4101 = RESISTOR: ROHS CHIP RES 4.7K 1/16W +/-5%
R4106 R4202 = RESISTOR_1: 贴片电阻; MARK: 51K; ROOM: USB+5V
U4100 U4101 = NANDFLASH_0: NAND Flash,2.7V,3.3V,3.6V,2G*8,N/A,-40℃~85℃,TSOP-48P; NAND FLASH: 1
C4200 C4201 = CAP_NP: RoHS CHIP CAP 10uF +10/-10% X5R
U4200 = TSD_0: NAND Flash,2.7V,3.3V,3.6V,2G*8,N/A,-40℃~85℃,TSOP-48P; NAND FLASH: 1; ROW: 1
B4500 = BEAD
C4500 C4502 = SMALL_CAP: 贴片电容
C4503 C4505 C4507-C4514 C4601 C4705 C5000-C5002 C5007 = CAP_NP: CAP,MLCC,100nF,+/-10%,X7R,6.3V,SMD0402
L4500 L4501 L5000 = INDUCTORS_OF_FERRITE
LED4500 LED4501 LED4503 = LED
R4500-R4508 = RES_1B
U4500 = LDO-PT5127
U4502 = LED_Drive-SGM3140
U4503 = SY7803-DFN14
U4504 = LED_Drive-SKY81290
C4600 C4700 C4701 = CAP_NP: CAP,MLCC,8pF,+/-10%,NPO,6.3V,SMD0402
C4602-C4606 = CAP_NP: ROOM: CHG
J4600 = CAMERA-MIPI-30P_1
R4600 R4702 R4703 = RESISTOR_0: RES,thick film,22Ohm,+/-5%,1/16W,SMD0402
R4601 R4602 R4700 R4701 = RESISTOR_0
T4600-T4619 T4700-T4719 T5000-T5014 = TESTPOINT1
C4702-C4704 = CAP_NP: CAP,MLCC,1uF,+/-10%,X5R,6.3V,SMD0402
J4700 = LCM0200CE1A0_1: Camera Conncetor, 24pin,SMT
C5004 = CAP_NP: RoHS CHIP CAP 1uF +10/-10% 25V X5R
C5006 = CAP_NP: CAP,MLCC,4.7uF,+/-10%,X5R,6.3V,SMD0603
D5000 = DIODE
J5000 = eDP_Flex
R5000 R5001 = RESISTOR_1
R5002-R5004 R5008 R5009 = RES_1B: ROHS CHIP RES 4.7K 1/16W 5%
R5005 = RES_1B: ROHS CHIP RES 82K 1/16W 5%
R5006 R5007 = RES_1B: ROHS CHIP RES 4.7R 1/4W 5%
U5000 = MP3202-QFN8_1

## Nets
AVDD28_DVP: B4500.2 C4505.1 C4606.2 J4600.17(AVDD_2.8V) T4619.1
GND: C3500.1 C3501.2 C3502.2 C3503.2 C3504.2 C3505.2 C3506.2 C3507.1 C3508.2 C3509.2 C3510.2 C3511.2 C3512.2 C3513.2 C3514.2 C3515.2 C3516.1 C3517.2 C3518.2 C3519.2 C3520.2 C3521.2 C3522.2 C3523.1 C3524.1 C3525.1 C3526.2 C3527.1 C3600.2 C3601.2 C3602.2 C3603.2 C3604.2 C3605.1 C3606.2 C3607.2 C3608.2 C3609.2 C3610.2 C3611.2 C3612.2 C3613.1 C3614.2 C3615.2 C3616.2 C3617.2 C3618.2 C3619.2 C3620.1 C3621.2 C3622.2 C3623.2 C3624.2 C3625.2 C3626.2 C3627.2 C3628.2 C3629.2 C3630.2 C3631.2 C3632.1 C3633.2 C3634.2 C3635.2 C3636.2 C3637.2 C3638.1 C3639.2 C3640.1 C3641.1 C3642.1 C4000.1 C4001.2 C4002.2 C4003.2 C4004.1 C4005.1 C4006.1 C4007.1 C4008.1 C4009.1 C4100.1 C4101.1 C4102.1 C4103.1 C4104.1 C4105.1 C4200.1 C4201.1 C4202.2 C4500.2 C4501.2 C4502.2 C4503.2 C4504.2 C4505.2 C4506.1 C4507.2 C4508.2 C4510.2 C4511.2 C4512.2 C4513.2 C4514.2 C4600.1 C4601.1 C4602.1 C4603.1 C4604.1 C4605.1 C4606.1 C4700.1 C4701.1 C4702.2 C4703.2 C4704.1 C4705.1 C5002.2 C5003.2 C5004.2 C5005.1 C5006.2 C5007.2 J4600.1(DGND) J4600.4(DNGD) J4600.7(DGND) J4600.10(DGND) J4600.13(DGND) J4600.15(DGND) J4600.16(DGND) J4600.19(DGND) J4600.23(DGND) J4600.25(DGND) J4600.28(DGND) J4700.2(AGND) J4700.15(DGND) J4700.25(GND) J4700.26(GND) J5000.1(GND) J5000.3(GND) J5000.8(GND) J5000.11(GND) J5000.15(GND) J5000.19(GND) J5000.23(GND) J5000.27(GND) J5000.28(GND) J5000.29(GND) J5000.36(GND) J5000.43(GND) J5000.51(GND) J5000.52(PAD) J5000.53(PAD) Q3501.2(E) Q3601.2(E) Q4500.2(E) Q4501.2(E) R3503.2 R3504.2 R3600.2 R3601.2 R3602.2 R3603.2 R4003.1 R4501.1 R4502.1 R4503.1 R4504.1 R4506.1 R4508.1 R5000.2 R5004.1 R5006.2 R5007.2 T4001.1 T4101.1 T4201.1 T4600.1 T5010.1 U3500.A2(VSS-ab) U3500.A4(VSSQ-b) U3500.A7(VSSQ-b) U3500.A13(VSSQ-b) U3500.A16(VSSQ-b) U3500.A20(VSSQ-b) U3500.A21(VSSQ-ab) U3500.A25(VSSQ-b) U3500.A26(VSSQ-ab) U3500.AA1(VSSQ-a) U3500.AB27(VSS-ab) U3500.AC1(VSSQ-a) U3500.AC27(VSSCA-a) U3500.AE1(VSSQ-a) U3500.AF1(VSS-ab) U3500.AF27(VSS-ab) U3500.AG3(VSSQ-a) U3500.AG7(VSSQ-a) U3500.AG10(VSSQ-a) U3500.AG11(VSS-ab) U3500.AG13(VSSCA-b) U3500.AG17(VSS-ab) U3500.AG18(VSSCA-b) U3500.AG22(VSSCA-b) U3500.AG25(VSS-ab) U3500.B11(VSSQ-b) U3500.E1(VSSQ-a) U3500.E27(VSSQ-b) U3500.G1(VSSQ-a) U3500.G27(VSSQ-b) U3500.J1(VSSQ-a) U3500.J27(VSSQ-b) U3500.L1(VSSQ-a) U3500.L27(VSSQ-b) U3500.N1(VSSQ-a) U3500.N27(VSS-ab) U3500.R1(VSSQ-a) U3500.R27(VSSCA-a) U3500.U1(VSS-ab) U3500.U2(VSSQ-a) U3500.U27(VSS-ab) U3500.W1(VSS-ab) U3500.W27(VSSCA-a) U3600.B2(VSS) U3600.B5(VSS) U3600.B6(VSSQ) U3600.B12(VSSQ) U3600.C3(VSSCA) U3600.C5(VSS) U3600.C6(VSSQ) U3600.D3(VSSCA) U3600.D12(VSSQ) U3600.E4(VSS) U3600.E5(VSS) U3600.E6(VSSQ) U3600.F4(VSSCA) U3600.F5(VSS) U3600.F6(VSSQ) U3600.F12(VSSQ) U3600.G3(VSSCA) U3600.G4(VSSCA) U3600.G6(VSSQ) U3600.G9(VSSQ) U3600.H2(VSS) U3600.H10(VSSQ) U3600.J4(VSSCA) U3600.J12(VSS) U3600.K2(VSS) U3600.K10(VSSQ) U3600.L6(VSS) U3600.L9(VSSQ) U3600.M4(VSSCA) U3600.M5(VSS) U3600.M6(VSSQ) U3600.M12(VSSQ) U3600.N4(VSS) U3600.N5(VSS) U3600.N6(VSSQ) U3600.P3(VSSCA) U3600.P12(VSSQ) U3600.R4(VSS) U3600.R5(VSS) U3600.R6(VSSQ) U3600.T2(VSS) U3600.T3(VSS) U3600.T4(VSS) U3600.T5(VSS) U3600.T6(VSSQ) U3600.T12(VSSQ) U3601.B2(VSS) U3601.B5(VSS) U3601.B6(VSSQ) U3601.B12(VSSQ) U3601.C3(VSSCA) U3601.C5(VSS) U3601.C6(VSSQ) U3601.D3(VSSCA) U3601.D12(VSSQ) U3601.E4(VSS) U3601.E5(VSS) U3601.E6(VSSQ) U3601.F4(VSSCA) U3601.F5(VSS) U3601.F6(VSSQ) U3601.F12(VSSQ) U3601.G3(VSSCA) U3601.G4(VSSCA) U3601.G6(VSSQ) U3601.G9(VSSQ) U3601.H2(VSS) U3601.H10(VSSQ) U3601.J4(VSSCA) U3601.J12(VSS) U3601.K2(VSS) U3601.K10(VSSQ) U3601.L6(VSS) U3601.L9(VSSQ) U3601.M4(VSSCA) U3601.M5(VSS) U3601.M6(VSSQ) U3601.M12(VSSQ) U3601.N4(VSS) U3601.N5(VSS) U3601.N6(VSSQ) U3601.P3(VSSCA) U3601.P12(VSSQ) U3601.R4(VSS) U3601.R5(VSS) U3601.R6(VSSQ) U3601.T2(VSS) U3601.T3(VSS) U3601.T4(VSS) U3601.T5(VSS) U3601.T6(VSSQ) U3601.T12(VSSQ) U4000.AA4(VSSQ) U4000.AA6(VSSQ) U4000.K4(VSSQ) U4000.M7(VSS) U4000.P5(VSS) U4000.R10(VSS) U4000.U8(VSS) U4000.Y2(VSSQ) U4000.Y5(VSSQ) U4001.2(GND) U4100.2(VSS1) U4100.13(VSS2) U4100.23(VSS3) U4100.25(VSS6) U4100.36(VSS4) U4100.48(VSS5) U4101.2(VSS1) U4101.13(VSS2) U4101.23(VSS3) U4101.25(VSS6) U4101.36(VSS4) U4101.48(VSS5) U4200.36(VSS) U4500.2(GND) U4501.2(GND) U4502.8(SGND) U4502.9(PGND) U4503.3(AGND) U4503.7(PGND) U4503.13(AGND) U4503.15(EPAD) U4504.4(AGND) U4504.7(PGND) U4504.9(AGND) U4504.12(FLGND) U5000.11(GND2) ; also on sheet 5 6 7 8 9 10 11 12 13 14 15 16 17 18 28 29 30 31 32 33 34 35 36 37 38 39 40 41 42 43 44 45 46 47 48
VCC15_DVP: C4506.2 C4602.2 J4600.22(DVDD_1.5V_CORE) T4616.1 U4501.5(OUT)
VCC18_DDR: C3502.1 C3503.1 C3504.1 C3505.1 C3506.1 C3524.2 C3600.1 C3601.1 C3602.1 C3603.1 C3604.1 C3607.1 C3608.1 C3609.1 C3610.1 C3611.1 C3641.2 R3502.2 R3605.2 U3500.AE26(VDD1-ab) U3500.AF12(VDD1-ab) U3500.AG26(VDD1-ab) U3500.B1(VDD1-ab) U3500.B2(VACC) U3500.B21(VDD1-ab) U3500.B26(VACC) U3500.V2(VDD1-ab) U3600.A3(VDD1) U3600.A4(VDD1) U3600.A5(VDD1) U3600.A6(VDD1) U3600.A10(VDD1) U3600.U3(VDD1) U3600.U4(VDD1) U3600.U5(VDD1) U3600.U6(VDD1) U3600.U10(VDD1) U3601.A3(VDD1) U3601.A4(VDD1) U3601.A5(VDD1) U3601.A6(VDD1) U3601.A10(VDD1) U3601.U3(VDD1) U3601.U4(VDD1) U3601.U5(VDD1) U3601.U6(VDD1) U3601.U10(VDD1) ; also on sheet 17 18
VCC18_DVP: C4500.1 C4603.2 C4703.1 J4600.24(DOVDD_1.8V) J4700.11(DOVDD) R4601.1 R4602.1 R4603.2 R4700.1 R4701.1 R4704.2 T4617.1 T4718.1 U4500.1(OUT2) ; also on sheet 9
VCC28_DVP: B4500.1 C4503.1 C4604.2 C4605.2 C4702.1 J4600.18(AF) J4700.4(AVDD) T4618.1 T4717.1 U4500.6(OUT1)
VCC_18: C3523.2 C3640.2 R3502.1 R3605.1 ; also on sheet 13 14 17 18 32 33 34 35 45 46
VCC_20: C4501.1 U4501.1(IN) ; also on sheet 13 14
VCC_BLIN: R5002.1 ; also on sheet 14
VCC_DDR: C3516.2 C3517.1 C3518.1 C3519.1 C3520.1 C3521.1 C3522.1 C3614.1 C3615.1 C3616.1 C3617.1 C3618.1 C3619.1 C3626.1 C3627.1 C3628.1 C3629.1 C3630.1 C3631.1 Q3500.3(DRAIN) Q3600.3(DRAIN) U3500.A3(VDD2-ab) U3500.A22(VDD2-ab) U3500.AA27(VDD2-ab) U3500.AD26(VDDCA-a) U3500.AD27(VDD2-ab) U3500.AF11(VDD2-ab) U3500.AF13(VDDCA-b) U3500.AF16(VDD2-ab) U3500.AF18(VDDCA-b) U3500.AF23(VDDCA-b) U3500.AF26(VDD2-ab) U3500.AG2(VDD2-ab) U3500.B27(VDD2-ab) U3500.M26(VDD2-ab) U3500.P26(VDDCA-a) U3500.V1(VDD2-ab) U3500.W2(VDD2-ab) U3500.Y26(VDDCA-a) U3600.A8(VDD2) U3600.A9(VDD2) U3600.D4(VDD2) U3600.D5(VDD2) U3600.D6(VDD2) U3600.F2(VDDCA) U3600.G2(VDDCA) U3600.G5(VDD2) U3600.H3(VDDCA) U3600.H5(VDD2) U3600.H6(VDD2) U3600.H12(VDD2) U3600.J5(VDD2) U3600.J6(VDD2) U3600.K5(VDD2) U3600.K6(VDD2) U3600.K12(VDD2) U3600.L2(VDDCA) U3600.L5(VDD2) U3600.M2(VDDCA) U3600.P4(VDD2) U3600.P5(VDD2) U3600.P6(VDD2) U3600.U8(VDD2) U3600.U9(VDD2) U3601.A8(VDD2) U3601.A9(VDD2) U3601.D4(VDD2) U3601.D5(VDD2) U3601.D6(VDD2) U3601.F2(VDDCA) U3601.G2(VDDCA) U3601.G5(VDD2) U3601.H3(VDDCA) U3601.H5(VDD2) U3601.H6(VDD2) U3601.H12(VDD2) U3601.J5(VDD2) U3601.J6(VDD2) U3601.K5(VDD2) U3601.K6(VDD2) U3601.K12(VDD2) U3601.L2(VDDCA) U3601.L5(VDD2) U3601.M2(VDDCA) U3601.P4(VDD2) U3601.P5(VDD2) U3601.P6(VDD2) U3601.U8(VDD2) U3601.U9(VDD2) ; also on sheet 7 13 14 15 16 17 18
VCC_DDRC: C3509.1 C3510.1 C3511.1 C3512.1 C3513.1 C3514.1 C3515.1 C3525.2 C3526.1 C3620.2 C3621.1 C3622.1 C3623.1 C3624.1 C3625.1 C3632.2 C3633.1 C3634.1 C3635.1 C3636.1 C3637.1 C3638.2 C3639.1 Q3500.2(SOURCE) Q3600.2(SOURCE) U3500.AB2(VDDQ-a) U3500.AF2(VDDQ-a) U3500.AF8(VDDQ-a) U3500.AG4(VDDQ-a) U3500.B3(VDDQ-b) U3500.B6(VDDQ-b) U3500.B9(VDDQ-b) U3500.B12(VDDQ-b) U3500.B15(VDDQ-b) U3500.B19(VDDQ-b) U3500.B24(VDDQ-b) U3500.D2(VDDQ-a) U3500.D26(VDDQ-b) U3500.F2(VDDQ-a) U3500.F26(VDDQ-b) U3500.K2(VDDQ-a) U3500.K26(VDDQ-b) U3500.M2(VDDQ-a) U3500.N26(VDDQ-b) U3500.P2(VDDQ-a) U3500.T2(VDDQ-a) U3600.A11(VDDQ) U3600.C12(VDDQ) U3600.E8(VDDQ) U3600.E12(VDDQ) U3600.G12(VDDQ) U3600.H8(VDDQ) U3600.H9(VDDQ) U3600.H11(VDDQ) U3600.J9(VDDQ) U3600.J10(VDDQ) U3600.K8(VDDQ) U3600.K11(VDDQ) U3600.L12(VDDQ) U3600.N8(VDDQ) U3600.N12(VDDQ) U3600.R12(VDDQ) U3600.U11(VDDQ) U3601.A11(VDDQ) U3601.C12(VDDQ) U3601.E8(VDDQ) U3601.E12(VDDQ) U3601.G12(VDDQ) U3601.H8(VDDQ) U3601.H9(VDDQ) U3601.H11(VDDQ) U3601.J9(VDDQ) U3601.J10(VDDQ) U3601.K8(VDDQ) U3601.K11(VDDQ) U3601.L12(VDDQ) U3601.N8(VDDQ) U3601.N12(VDDQ) U3601.R12(VDDQ) U3601.U11(VDDQ) ; also on sheet 7 15 16 17 18
VCC_IO: C4003.1 C4005.2 C4006.2 C4100.2 C4101.2 C4102.2 C4103.2 C4104.2 C4105.2 C4201.2 C4202.1 R4002.1 R4100.1 R4101.1 R4102.2 R4103.2 R4104.2 R4105.2 R4106.1 R4202.1 R4500.2 R4505.2 U4000.M6(VCC) U4000.N5(VCC) U4000.T10(VCC) U4000.U9(VCC) U4001.1(IN) U4001.3(EN) U4100.1(VCC1) U4100.12(VCC2) U4100.24(VCC3) U4100.34(VCCQ2) U4100.37(VCC4) U4100.38(VCCQ5) U4100.39(VCCQ3) U4101.1(VCC1) U4101.12(VCC2) U4101.24(VCC3) U4101.34(VCCQ2) U4101.37(VCC4) U4101.38(VCCQ5) U4101.39(VCCQ3) U4200.28(tSD_3V3) ; also on sheet 11 13 14 31 32 33 34 35 41 42 43
VCC_LCD: C5006.1 C5007.1 J5000.4(VIN) J5000.5(VIN) J5000.6(VIN) J5000.7(VIN) R5001.2 T5001.1 ; also on sheet 5 10 13 14 28 29 30
VCC_LEDA: C5004.1 D5000.2(K) J5000.45(LEDA2) J5000.46(LEDA2) J5000.48(LEDA1) J5000.49(LEDA1) T5012.1 U5000.8(OVP) ; also on sheet 28 29 30
VCC_LEDK: J5000.30(LEDC6B) J5000.31(LEDC5B) J5000.32(LEDC4B) J5000.33(LEDC3B) J5000.34(LEDC2B) J5000.35(LEDC1B) J5000.37(LEDC6A) J5000.38(LEDC5A) J5000.39(LEDC4A) J5000.40(LEDC3A) J5000.41(LEDC2A) J5000.42(LEDC1A) R5005.2 R5006.1 R5007.1 T5011.1 ; also on sheet 28 29 30
VCC_SYS: C4502.1 C4507.1 C4508.1 C4510.1 C4513.1 L4500.1 L4501.1 R5003.1 U4500.5(VIN) U4502.1(VIN) U4503.4(VIN) U4504.5(VIN) ; also on sheet 13 14 28 29 30 33 34 35 43
VCCIO_FLASH: C4001.1 C4002.1 C4007.2 C4008.2 C4009.2 R4000.1 R4002.2 R4106.2 R4201.1 R4202.2 RP4000.1 RP4000.2 RP4000.3 RP4000.4 RP4001.1 RP4001.2 RP4001.3 RP4001.4 RP4200.1 RP4200.2 RP4200.3 RP4200.4 U4000.AA3(VCCQ) U4000.AA5(VCCQ) U4000.K6(VCCQ) U4000.W4(VCCQ) U4000.Y4(VCCQ) U4001.5(OUT) ; also on sheet 8
VCCIO_PMU: R3505.2 R3607.2 R4507.1 ; also on sheet 6 11 13 14 17 18 33 34 35 41 43 46
BL_EN: R5004.2 U5000.9(EN) ; also on sheet 11 14 28 29 30
CIF_CLKI: C4700.2 R4702.2 ; also on sheet 9
CIF_CLKIN: J4700.17(PCLK) R4702.1 T4711.1
CIF_CLKO: R4600.2 R4703.2 ; also on sheet 9
CIF_CLKOUT: C4701.2 J4700.13(XCLK1) R4703.1 T4708.1
CIF_D0: J4700.19(Y2) T4713.1 ; also on sheet 9
CIF_D1: J4700.21(Y3) T4715.1 ; also on sheet 9
CIF_D2: J4700.22(Y4) T4716.1 ; also on sheet 9
CIF_D3: J4700.20(Y5) T4714.1 ; also on sheet 9
CIF_D4: J4700.18(Y6) T4712.1 ; also on sheet 9
CIF_D5: J4700.16(Y7) T4710.1 ; also on sheet 9
CIF_D6: J4700.14(Y8) T4709.1 ; also on sheet 9
CIF_D7: J4700.12(Y9) T4707.1 ; also on sheet 9
CIF_DVDD: C4704.2 J4700.10(DVDD) T4719.1
CIF_HREF: J4700.9(HREF) T4706.1 ; also on sheet 9
CIF_PDN0: J4700.8(PWDN0) T4705.1 ; also on sheet 9
CIF_PDN1: J4600.14(PWDN) J4700.1(PWDN1) T4615.1 T4700.1 ; also on sheet 9
CIF_RST: C4705.2 J4700.6(RESET) R4704.1 T4704.1
CIF_VSYNC: J4700.7(VSYNC) T4701.1 ; also on sheet 9
DDR0_A0: U3500.AF25(DDR_A0-b) U3600.R2(DDR_A0) ; also on sheet 7 15 16 17 18
DDR0_A1: U3500.AG24(DDR_A1-b) U3600.P2(DDR_A1) ; also on sheet 7 15 16 17 18
DDR0_A2: U3500.AF24(DDR_A2-b) U3600.N2(DDR_A2) ; also on sheet 7 15 16 17 18
DDR0_A3: U3500.AG23(DDR_A3-b) U3600.N3(DDR_A3) ; also on sheet 7 15 16 17 18
DDR0_A4: U3500.AF22(DDR_A4-b) U3600.M3(DDR_A4) ; also on sheet 7 15 16 17 18
DDR0_A5: U3500.AG16(DDR_A5-b) U3600.F3(DDR_A5) ; also on sheet 7 15 16 17 18
DDR0_A6: U3500.AG15(DDR_A6-b) U3600.E3(DDR_A6) ; also on sheet 7 15 16 17 18
DDR0_A7: U3500.AF15(DDR_A7-b) U3600.E2(DDR_A7) ; also on sheet 7 15 16 17 18
DDR0_A8: U3500.AG14(DDR_A8-b) U3600.D2(DDR_A8) ; also on sheet 7 15 16 17 18
DDR0_A9: U3500.AF14(DDR_A9-b) U3600.C2(DDR_A9) ; also on sheet 7 15 16 17 18
DDR0_CKE0: U3500.AG20(DDR_CKE0-b) U3600.K3(DDR_CKE0) ; also on sheet 7 15 16 17 18
DDR0_CKE1: U3500.AF20(DDR_CKE1-b) U3600.K4(DDR_CKE1) ; also on sheet 7 15 17 18
DDR0_CLK: R3500.2 R3606.2 U3500.AF19(DDR_CLK-b) U3600.J3(DDR_CLK) ; also on sheet 7 15 16 17 18
DDR0_CLKN: R3500.1 R3606.1 U3500.AG19(DDR_CLKn-b) U3600.J2(DDR_CLKn) ; also on sheet 7 15 16 17 18
DDR0_CS0N: U3500.AF21(DDR_CS0-b) U3600.L3(DDR_CS0) ; also on sheet 7 15 16 17 18
DDR0_CS1N: U3500.AG21(DDR_CS1-b) U3600.L4(DDR_CS1) ; also on sheet 7 15 17 18
DDR0_D0: U3500.F27(DDR_D0-b) U3600.P9(DDR_D0) ; also on sheet 7 15 16 17 18
DDR0_D1: U3500.E26(DDR_D1-b) U3600.N9(DDR_D1) ; also on sheet 7 15 16 17 18
DDR0_D2: U3500.E25(DDR_D2-b) U3600.N10(DDR_D2) ; also on sheet 7 15 16 17 18
DDR0_D3: U3500.D27(DDR_D3-b) U3600.N11(DDR_D3) ; also on sheet 7 15 16 17 18
DDR0_D4: U3500.C27(DDR_D4-b) U3600.M8(DDR_D4) ; also on sheet 7 15 16 17 18
DDR0_D5: U3500.C26(DDR_D5-b) U3600.M9(DDR_D5) ; also on sheet 7 15 16 17 18
DDR0_D6: U3500.B25(DDR_D6-b) U3600.M10(DDR_D6) ; also on sheet 7 15 16 17 18
DDR0_D7: U3500.A24(DDR_D7-b) U3600.M11(DDR_D7) ; also on sheet 7 15 16 17 18
DDR0_D8: U3500.B17(DDR_D8-b) U3600.F11(DDR_D8) ; also on sheet 7 15 16 17 18
DDR0_D9: U3500.A17(DDR_D9-b) U3600.F10(DDR_D9) ; also on sheet 7 15 16 17 18
DDR0_D10: U3500.B16(DDR_D10-b) U3600.F9(DDR_D10) ; also on sheet 7 15 16 17 18
DDR0_D11: U3500.A15(DDR_D11-b) U3600.F8(DDR_D11) ; also on sheet 7 15 16 17 18
DDR0_D12: U3500.B14(DDR_D12-b) U3600.E11(DDR_D12) ; also on sheet 7 15 16 17 18
DDR0_D13: U3500.A14(DDR_D13-b) U3600.E10(DDR_D13) ; also on sheet 7 15 16 17 18
DDR0_D14: U3500.B13(DDR_D14-b) U3600.E9(DDR_D14) ; also on sheet 7 15 16 17 18
DDR0_D15: U3500.A12(DDR_D15-b) U3600.D9(DDR_D15) ; also on sheet 7 15 16 17 18
DDR0_D16: U3500.N25(DDR_D16-b) U3600.T8(DDR_D16/NC) ; also on sheet 7 15 16 17 18
DDR0_D17: U3500.M27(DDR_D17-b) U3600.T9(DDR_D17/NC) ; also on sheet 7 15 16 17 18
DDR0_D18: U3500.L26(DDR_D18-b) U3600.T10(DDR_D18/NC) ; also on sheet 7 15 16 17 18
DDR0_D19: U3500.L25(DDR_D19-b) U3600.T11(DDR_D19/NC) ; also on sheet 7 15 16 17 18
DDR0_D20: U3500.K27(DDR_D20-b) U3600.R8(DDR_D20/NC) ; also on sheet 7 15 16 17 18
DDR0_D21: U3500.J25(DDR_D21-b) U3600.R9(DDR_D21/NC) ; also on sheet 7 15 16 17 18
DDR0_D22: U3500.J26(DDR_D22-b) U3600.R10(DDR_D22/NC) ; also on sheet 7 15 16 17 18
DDR0_D23: U3500.H27(DDR_D23-b) U3600.R11(DDR_D23/NC) ; also on sheet 7 15 16 17 18
DDR0_D24: U3500.A9(DDR_D24-b) U3600.C11(DDR_D24/NC) ; also on sheet 7 15 16 17 18
DDR0_D25: U3500.A8(DDR_D25-b) U3600.C10(DDR_D25/NC) ; also on sheet 7 15 16 17 18
DDR0_D26: U3500.B8(DDR_D26-b) U3600.C9(DDR_D26/NC) ; also on sheet 7 15 16 17 18
DDR0_D27: U3500.B7(DDR_D27-b) U3600.C8(DDR_D27/NC) ; also on sheet 7 15 16 17 18
DDR0_D28: U3500.A6(DDR_D28-b) U3600.B11(DDR_D28/NC) ; also on sheet 7 15 16 17 18
DDR0_D29: U3500.A5(DDR_D29-b) U3600.B10(DDR_D29/NC) ; also on sheet 7 15 16 17 18
DDR0_D30: U3500.B5(DDR_D30-b) U3600.B9(DDR_D30/NC) ; also on sheet 7 15 16 17 18
DDR0_D31: U3500.B4(DDR_D31-b) U3600.B8(DDR_D31/NC) ; also on sheet 7 15 16 17 18
DDR0_DM0: U3500.B22(DDR_DM0-b) U3600.L8(DDR_DM0) ; also on sheet 7 15 16 17 18
DDR0_DM1: U3500.A19(DDR_DM1-b) U3600.G8(DDR_DM1) ; also on sheet 7 15 16 17 18
DDR0_DM2: U3500.G25(DDR_DM2-b) U3600.P8(DDR_DM2/NC) ; also on sheet 7 15 16 17 18
DDR0_DM3: U3500.A11(DDR_DM3-b) U3600.D8(DDR_DM3/NC) ; also on sheet 7 15 16 17 18
DDR0_DQS0M: U3500.A23(DDR_DQS0n-b) U3600.L11(DDR_DQS0n) ; also on sheet 7 15 16 17 18
DDR0_DQS0P: U3500.B23(DDR_DQS0-b) U3600.L10(DDR_DQS0) ; also on sheet 7 15 16 17 18
DDR0_DQS1M: U3500.A18(DDR_DQS1n-b) U3600.G11(DDR_DQS1n) ; also on sheet 7 15 16 17 18
DDR0_DQS1P: U3500.B18(DDR_DQS1-b) U3600.G10(DDR_DQS1) ; also on sheet 7 15 16 17 18
DDR0_DQS2M: U3500.H26(DDR_DQS2n-b) U3600.P11(DDR_DQS2n) ; also on sheet 7 15 16 17 18
DDR0_DQS2P: U3500.G26(DDR_DQS2-b) U3600.P10(DDR_DQS2) ; also on sheet 7 15 16 17 18
DDR0_DQS3M: U3500.A10(DDR_DQS3n-b) U3600.D11(DDR_DQS3n) ; also on sheet 7 15 16 17 18
DDR0_DQS3P: U3500.B10(DDR_DQS3-b) U3600.D10(DDR_DQS3) ; also on sheet 7 15 16 17 18
DDR0_ODT0: U3600.J8(DDR_ODT) ; also on sheet 7 15 16
DDR1_A0: U3500.P27(DDR_A0-a) U3601.R2(DDR_A0) ; also on sheet 7 15 16 17 18
DDR1_A1: U3500.R25(DDR_A1-a) U3601.P2(DDR_A1) ; also on sheet 7 15 16 17 18
DDR1_A2: U3500.R26(DDR_A2-a) U3601.N2(DDR_A2) ; also on sheet 7 15 16 17 18
DDR1_A3: U3500.T26(DDR_A3-a) U3601.N3(DDR_A3) ; also on sheet 7 15 16 17 18
DDR1_A4: U3500.T27(DDR_A4-a) U3601.M3(DDR_A4) ; also on sheet 7 15 16 17 18
DDR1_A5: U3500.Y27(DDR_A5-a) U3601.F3(DDR_A5) ; also on sheet 7 15 16 17 18
DDR1_A6: U3500.AA26(DDR_A6-a) U3601.E3(DDR_A6) ; also on sheet 7 15 16 17 18
DDR1_A7: U3500.AB26(DDR_A7-a) U3601.E2(DDR_A7) ; also on sheet 7 15 16 17 18
DDR1_A8: U3500.AC25(DDR_A8-a) U3601.D2(DDR_A8) ; also on sheet 7 15 16 17 18
DDR1_A9: U3500.AC26(DDR_A9-a) U3601.C2(DDR_A9) ; also on sheet 7 15 16 17 18
DDR1_CKE0: U3500.V26(DDR_CKE0-a) U3601.K3(DDR_CKE0) ; also on sheet 7 15 16 17 18
DDR1_CKE1: U3500.V27(DDR_CKE1-a) U3601.K4(DDR_CKE1) ; also on sheet 7 15 17 18
DDR1_CLK: R3501.2 R3604.2 U3500.W26(DDR_CLK-a) U3601.J3(DDR_CLK) ; also on sheet 7 15 16 17 18
DDR1_CLKN: R3501.1 R3604.1 U3500.W25(DDR_CLKn-a) U3601.J2(DDR_CLKn) ; also on sheet 7 15 16 17 18
DDR1_CS0N: U3500.U25(DDR_CS0-a) U3601.L3(DDR_CS0) ; also on sheet 7 15 16 17 18
DDR1_CS1N: U3500.U26(DDR_CS1-a) U3601.L4(DDR_CS1) ; also on sheet 7 15 17 18
DDR1_D0: U3500.AB1(DDR_D8-a) U3601.C11(DDR_D24/NC) ; also on sheet 7 15 16 17 18
DDR1_D1: U3500.AA2(DDR_D9-a) U3601.C10(DDR_D25/NC) ; also on sheet 7 15 16 17 18
DDR1_D2: U3500.AA3(DDR_D10-a) U3601.C9(DDR_D26/NC) ; also on sheet 7 15 16 17 18
DDR1_D3: U3500.AC2(DDR_D11-a) U3601.C8(DDR_D27/NC) ; also on sheet 7 15 16 17 18
DDR1_D4: U3500.AC3(DDR_D12-a) U3601.B11(DDR_D28/NC) ; also on sheet 7 15 16 17 18
DDR1_D5: U3500.AD1(DDR_D13-a) U3601.B10(DDR_D29/NC) ; also on sheet 7 15 16 17 18
DDR1_D6: U3500.AD2(DDR_D14-a) U3601.B9(DDR_D30/NC) ; also on sheet 7 15 16 17 18
DDR1_D7: U3500.AE2(DDR_D15-a) U3601.B8(DDR_D31/NC) ; also on sheet 7 15 16 17 18
DDR1_D8: U3500.J3(DDR_D0-a) U3601.T8(DDR_D16/NC) ; also on sheet 7 15 16 17 18
DDR1_D9: U3500.K1(DDR_D1-a) U3601.T9(DDR_D17/NC) ; also on sheet 7 15 16 17 18
DDR1_D10: U3500.L2(DDR_D2-a) U3601.T10(DDR_D18/NC) ; also on sheet 7 15 16 17 18
DDR1_D11: U3500.L3(DDR_D3-a) U3601.T11(DDR_D19/NC) ; also on sheet 7 15 16 17 18
DDR1_D12: U3500.M1(DDR_D4-a) U3601.R8(DDR_D20/NC) ; also on sheet 7 15 16 17 18
DDR1_D13: U3500.N2(DDR_D5-a) U3601.R9(DDR_D21/NC) ; also on sheet 7 15 16 17 18
DDR1_D14: U3500.N3(DDR_D6-a) U3601.R10(DDR_D22/NC) ; also on sheet 7 15 16 17 18
DDR1_D15: U3500.P1(DDR_D7-a) U3601.R11(DDR_D23/NC) ; also on sheet 7 15 16 17 18
DDR1_D16: U3500.AG5(DDR_D24-a) U3601.F11(DDR_D8) ; also on sheet 7 15 16 17 18
DDR1_D17: U3500.AF6(DDR_D25-a) U3601.F10(DDR_D9) ; also on sheet 7 15 16 17 18
DDR1_D18: U3500.AG6(DDR_D26-a) U3601.F9(DDR_D10) ; also on sheet 7 15 16 17 18
DDR1_D19: U3500.AF7(DDR_D27-a) U3601.F8(DDR_D11) ; also on sheet 7 15 16 17 18
DDR1_D20: U3500.AG8(DDR_D28-a) U3601.E11(DDR_D12) ; also on sheet 7 15 16 17 18
DDR1_D21: U3500.AF9(DDR_D29-a) U3601.E10(DDR_D13) ; also on sheet 7 15 16 17 18
DDR1_D22: U3500.AG9(DDR_D30-a) U3601.E9(DDR_D14) ; also on sheet 7 15 16 17 18
DDR1_D23: U3500.AF10(DDR_D31-a) U3601.D9(DDR_D15) ; also on sheet 7 15 16 17 18
DDR1_D24: U3500.C1(DDR_D16-a) U3601.P9(DDR_D0) ; also on sheet 7 15 16 17 18
DDR1_D25: U3500.C2(DDR_D17-a) U3601.N9(DDR_D1) ; also on sheet 7 15 16 17 18
DDR1_D26: U3500.D1(DDR_D18-a) U3601.N10(DDR_D2) ; also on sheet 7 15 16 17 18
DDR1_D27: U3500.E3(DDR_D19-a) U3601.N11(DDR_D3) ; also on sheet 7 15 16 17 18
DDR1_D28: U3500.E2(DDR_D20-a) U3601.M8(DDR_D4) ; also on sheet 7 15 16 17 18
DDR1_D29: U3500.F1(DDR_D21-a) U3601.M9(DDR_D5) ; also on sheet 7 15 16 17 18
DDR1_D30: U3500.G2(DDR_D22-a) U3601.M10(DDR_D6) ; also on sheet 7 15 16 17 18
DDR1_D31: U3500.G3(DDR_D23-a) U3601.M11(DDR_D7) ; also on sheet 7 15 16 17 18
DDR1_DM0: U3500.W3(DDR_DM1-a) U3601.D8(DDR_DM3/NC) ; also on sheet 7 15 16 17 18
DDR1_DM1: U3500.T1(DDR_DM0-a) U3601.P8(DDR_DM2/NC) ; also on sheet 7 15 16 17 18
DDR1_DM2: U3500.AF3(DDR_DM3-a) U3601.G8(DDR_DM1) ; also on sheet 7 15 16 17 18
DDR1_DM3: U3500.J2(DDR_DM2-a) U3601.L8(DDR_DM0) ; also on sheet 7 15 16 17 18
DDR1_DQS0M: U3500.Y1(DDR_DQS1n-a) U3601.D11(DDR_DQS3n) ; also on sheet 7 15 16 17 18
DDR1_DQS0P: U3500.Y2(DDR_DQS1-a) U3601.D10(DDR_DQS3) ; also on sheet 7 15 16 17 18
DDR1_DQS1M: U3500.R2(DDR_DQS0n-a) U3601.P11(DDR_DQS2n) ; also on sheet 7 15 16 17 18
DDR1_DQS1P: U3500.R3(DDR_DQS0-a) U3601.P10(DDR_DQS2) ; also on sheet 7 15 16 17 18
DDR1_DQS2M: U3500.AF5(DDR_DQS3n-a) U3601.G11(DDR_DQS1n) ; also on sheet 7 15 16 17 18
DDR1_DQS2P: U3500.AF4(DDR_DQS3-a) U3601.G10(DDR_DQS1) ; also on sheet 7 15 16 17 18
DDR1_DQS3M: U3500.H2(DDR_DQS2n-a) U3601.L11(DDR_DQS0n) ; also on sheet 7 15 16 17 18
DDR1_DQS3P: U3500.H1(DDR_DQS2-a) U3601.L10(DDR_DQS0) ; also on sheet 7 15 16 17 18
DDR1_ODT0: U3601.J8(DDR_ODT) ; also on sheet 7 15 16
DDRIO_PWROFF: R3506.2 R3608.2 ; also on sheet 6 15 16 17 18
DVP_PWR: U4500.3(EN2) U4500.4(EN1) U4501.3(EN) ; also on sheet 6
EDP_AUXN: C5001.2 J5000.10(AUX_N) R5001.1 T5013.1
EDP_AUXP: C5000.2 J5000.9(AUX_P) R5000.1 T5014.1
EDP_HPD: J5000.2(HPD) T5000.1
EDP_TX0N: J5000.12(LANE0_N) T5002.1 ; also on sheet 10
EDP_TX0P: J5000.14(LANE0_P) T5003.1 ; also on sheet 10
EDP_TX1N: J5000.16(LANE1_N) T5004.1 ; also on sheet 10
EDP_TX1P: J5000.18(LANE1_P) T5005.1 ; also on sheet 10
EDP_TX2N: J5000.20(LANE2_N) T5006.1 ; also on sheet 10
EDP_TX2P: J5000.22(LANE2_P) T5007.1 ; also on sheet 10
EDP_TX3N: J5000.24(LANE3_N) T5008.1 ; also on sheet 10
EDP_TX3P: J5000.26(LANE3_P) T5009.1 ; also on sheet 10
EDPAUXN: C5001.1 ; also on sheet 10
EDPAUXP: C5000.1 ; also on sheet 10
FLASH0_ALE: U4101.17(ALE) ; also on sheet 8
FLASH0_CLE: T4100.1 U4101.16(CLE) ; also on sheet 8
FLASH0_CS0: U4101.9(~{CE0}) ; also on sheet 8
FLASH0_CS1: U4101.10(~{CE1}) ; also on sheet 8
FLASH0_CS2/EMMC_CMD: R4000.2 R4201.2 U4000.W5(CMD) U4101.14(~{CE2}) U4200.33(tSD_CMD) ; also on sheet 8
FLASH0_CS3/EMMC_RST: U4101.15(~{CE3}) ; also on sheet 8
FLASH0_D0: RP4000.8 RP4200.8 U4000.H3(DATA0) U4101.29(I/O0) U4200.47(tSD_D0) ; also on sheet 8
FLASH0_D1: RP4000.7 RP4200.7 U4000.H4(DATA1) U4101.30(I/O1) U4200.46(tSD_D1) ; also on sheet 8
FLASH0_D2: RP4000.6 RP4200.6 U4000.H5(DATA2) U4101.31(I/O2) U4200.45(tSD_D2) ; also on sheet 8
FLASH0_D3: RP4000.5 RP4200.5 U4000.J2(DATA3) U4101.32(I/O3) U4200.27(tSD_D3) ; also on sheet 8
FLASH0_D4: RP4001.5 U4000.J3(DATA4) U4101.41(I/O4) ; also on sheet 8
FLASH0_D5: RP4001.6 U4000.J4(DATA5) U4101.42(I/O5) ; also on sheet 8
FLASH0_D6: RP4001.7 U4000.J5(DATA6) U4101.43(I/O6) ; also on sheet 8
FLASH0_D7: RP4001.8 U4000.J6(DATA7) U4101.44(I/O7) ; also on sheet 8
FLASH0_DQS/EMMC_CLKO: R4001.1 R4200.2 T4000.1 T4200.1 U4101.35(DQS) ; also on sheet 8
FLASH0_RDN: U4101.8(~{RE}) ; also on sheet 8
FLASH0_RDY: R4100.2 U4101.4(R/~{B}1) U4101.5(R/~{B}2) U4101.6(R/~{B}3) U4101.7(R/~{B}4) ; also on sheet 8
FLASH0_WP/EMMC_PWREN: R4003.2 U4000.U5(RST_n) U4101.19(~{WP}) ; also on sheet 8
FLASH0_WRN: U4101.18(~{WE}) ; also on sheet 8
FLASH1_ALE: U4100.17(ALE) ; also on sheet 8
FLASH1_CLE: U4100.16(CLE) ; also on sheet 8
FLASH1_CSn0: U4100.9(~{CE0}) ; also on sheet 8
FLASH1_CSn1: U4100.10(~{CE1}) ; also on sheet 8
FLASH1_D0: U4100.29(I/O0) ; also on sheet 8
FLASH1_D1: U4100.30(I/O1) ; also on sheet 8
FLASH1_D2: U4100.31(I/O2) ; also on sheet 8
FLASH1_D3: U4100.32(I/O3) ; also on sheet 8
FLASH1_D4: U4100.41(I/O4) ; also on sheet 8
FLASH1_D5: U4100.42(I/O5) ; also on sheet 8
FLASH1_D6: U4100.43(I/O6) ; also on sheet 8
FLASH1_D7: U4100.44(I/O7) ; also on sheet 8
FLASH1_DQS: U4100.35(DQS) ; also on sheet 8
FLASH1_RDN: U4100.8(~{RE}) ; also on sheet 8
FLASH1_RDY: R4101.2 U4100.4(R/~{B}1) U4100.5(R/~{B}2) U4100.6(R/~{B}3) U4100.7(R/~{B}4) ; also on sheet 8
FLASH1_WP: U4100.19(~{WP}) ; also on sheet 8
FLASH1_WRN: U4100.18(~{WE}) ; also on sheet 8
FLASH_EN: R4508.2 U4502.5(EN) U4503.11(ENM) U4504.2(EN/SET) ; also on sheet 11
FLASH_TRIGOUT: Q4500.1(B) Q4501.1(B) R4507.2 U4502.4(FLASH) ; also on sheet 11
I2C3_SCL_CAM: J4600.20(SIO_C) J4700.5(SIO_C) R4601.2 R4700.2 T4613.1 T4703.1 ; also on sheet 9
I2C3_SDA_CAM: J4600.21(SIO_D) J4700.3(SIO_D) R4602.2 R4701.2 T4611.1 T4702.1 ; also on sheet 9
LCDC_BL: R5008.1 ; also on sheet 11 28 29 30
MIPI_MCLK: C4600.2 J4600.11(MCLK) R4600.1 T4612.1
MIPI_RST: C4601.2 J4600.12(RESET) R4603.1 T4614.1
MIPI_TX/RX_CLKN: J4600.30(MCLK-) T4601.1 ; also on sheet 10 29
MIPI_TX/RX_CLKP: J4600.29(MCLK+) T4603.1 ; also on sheet 10 29
MIPI_TX/RX_D0N: J4600.3(MD0-) T4604.1 ; also on sheet 10 29
MIPI_TX/RX_D0P: J4600.2(MD0+) T4602.1 ; also on sheet 10 29
MIPI_TX/RX_D1N: J4600.26(MD1-) T4607.1 ; also on sheet 10 29
MIPI_TX/RX_D1P: J4600.27(MD1+) T4605.1 ; also on sheet 10 29
MIPI_TX/RX_D2N: J4600.6(MD2-) T4608.1 ; also on sheet 10 29
MIPI_TX/RX_D2P: J4600.5(MD2+) T4606.1 ; also on sheet 10 29
MIPI_TX/RX_D3N: J4600.9(MD3-) T4610.1 ; also on sheet 10 29
MIPI_TX/RX_D3P: J4600.8(MD3+) T4609.1 ; also on sheet 10 29
VREF_DDR0: C3500.2 C3606.1 U3500.U3(DDR_VREFDQ-a) U3600.J11(DDR_VREFDQ) ; also on sheet 7 17 18
VREF_DDR1: C3501.1 C3613.2 U3500.B20(DDR_VREFDQ-b) U3601.J11(DDR_VREFDQ) ; also on sheet 7 17 18
VREFAO_DDR0: C3507.2 C3605.2 U3500.AA25(DDR_VREFCA-a) U3600.H4(DDR_VREFCA) ; also on sheet 7 15 16 17 18
VREFAO_DDR1: C3508.1 C3612.1 U3500.AF17(DDR_VREFCA-b) U3601.H4(DDR_VREFCA) ; also on sheet 7 15 16 17 18
N60277901: R4102.1 U4101.45(VCCQ4)
N60277918: R4104.1 U4101.28(VCCQ1)
N60695535: R4105.1 U4100.28(VCCQ1)
N60695555: R4103.1 U4100.45(VCCQ4)
N60876340: C4000.2 U4000.K2(VDDi)
N60876490: R4001.2 U4000.W6(CLK)
N60891123: C5002.1 C5003.1 L5000.1 R5002.2 R5003.2 U5000.7(IN)
N60891212: C5005.2 R5008.2 R5009.1
N60891218: R5005.1 R5009.2 U5000.2(FB)
N60891220: D5000.1(A) L5000.2 U5000.4(LX1) U5000.5(LX2)
N60957132: R4200.1 U4200.40(tSD_CLK)
N60957179: C4200.2 U4200.26(tSD_SDIP)
N61749301: R3602.1 U3600.B4(DDR_ZQ1)
N61749331: R3600.1 U3600.B3(DDR_ZQ0)
N61751480: R3603.1 U3601.B4(DDR_ZQ1)
N61751516: R3601.1 U3601.B3(DDR_ZQ0)
N61788138: L4500.2 U4503.5(LX1) U4503.6(LX2)
N61788156: C4512.1 LED4501.2(A) U4503.8(OUT1) U4503.9(OUT2)
N61788191: LED4501.1(K) U4503.12(LED1) U4503.14(LED2)
N61934592: Q4500.3(C) R4500.1 U4503.10(ENF)
N61934629: R4501.2 U4503.2(ISETF)
N61934838: R4502.2 U4503.1(ISETM)
N61953567: C4504.1 U4501.4(BP)
N62247211: C4509.2 U4502.2(C1)
N62247216: C4509.1 U4502.3(C2)
N62247362: C4511.1 LED4500.2(A) U4502.10(VOUT)
N62247718: R4503.2 U4502.6(RSET)
N62247839: LED4500.1(K) R4504.2 U4502.7(FB)
N62249333: L4501.2 U4504.6(SW)
N62249491: C4514.1 LED4503.2(A) U4504.8(VOUT)
N62249518: LED4503.1(K) U4504.13(FL)
N62249843: R4506.2 U4504.14(RSET)
N62250119: Q4501.3(C) R4505.1 U4504.3(FLEN)
N62661976: C3642.2 Q3600.1(GATE) Q3601.3(C) R3607.1
N62661978: Q3601.1(B) R3608.1
N63657549: R3504.1 U3500.AG12(DDR_ZQ-b)
N63657552: R3503.1 U3500.AE27(DDR_ZQ-a)
N63657783: C3527.2 Q3500.1(GATE) Q3501.3(C) R3505.1
N63657784: Q3501.1(B) R3506.1
N64095755: C4004.2 U4001.4(BP)

Not connected (* = marked no-connect by the designer): J4700 23(Y1)* 24(Y0)*; J5000 13(NC)* 17(NC)* 21(NC)* 25(NC)* 44(NC)* 47(NC)* 50(NC)*; U3500 A1(NC)* A27(NC)* AG1(NC)* AG27(NC)*; U3600 A1(NU)* A2(NU)* A12(NU)* A13(NU)* B1(NU)* B13(NU)* C4(NC)* K9(NC)* R3(NC)* T1(NU)* T13(NU)* U1(NU)* U2(NU)* U12(NU)* U13(NU)*; U3601 A1(NU)* A2(NU)* A12(NU)* A13(NU)* B1(NU)* B13(NU)* C4(NC)* K9(NC)* R3(NC)* T1(NU)* T13(NU)* U1(NU)* U2(NU)* U12(NU)* U13(NU)*; U4100 3(NC1)* 11(NC2)* 14(~{CE2})* 15(~{CE3})* 20(NC3)* 21(NC4)* 22(NC5)* 26(NC6)* 27(VSSQ1)* 33(VSSQ2)* 40(VSSQ3)* 46(VSSQ4)* 47(NC13)*; U4101 3(NC1)* 11(NC2)* 20(NC3)* 21(NC4)* 22(NC5)* 26(NC6)* 27(VSSQ1)* 33(VSSQ2)* 40(VSSQ3)* 46(VSSQ4)* 47(NC13)*; U4200 1(NC1)* 2(NC2)* 3(NC3)* 4(NC4)* 5(NC5)* 6(NC6)* 7(NC7)* 8(NC8)* 9(NC9)* 10(NC10)* 11(NC11)* 12(NC12)* 13(NC13)* 14(NC14)* 15(NC15)* 16(NC16)* 17(NC17)* 18(NC18)* 19(NC19)* 20(NC20)* 21(NC21)* 22(NC22)* 23(NC23)* 24(NC24)* 25(NC25)* 29(NC26)* 30(NC27)* 31(NC28)* 32(NC29)* 34(NC30)* 35(NC31)* 37(NC32)* 38(NC33)* 39(NC34)* 41(NC35)* 42(NC36)* 43(NC37)* 44(NC38)* 48(NC39)*; U4504 1(NC1)* 10(FLINH)* 11(NC2)*; U5000 1(NC1)* 3(NC2)* 6(NC3)* 10(NC4)*

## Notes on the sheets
sheet 21
- eMMC FLASH
- Note:
  Reserve PAD for Update.
sheet 22
- NAND FLASH
- note：if use toshiba and sandisk DDR mode,
  VCCQ1 and VCCQ4 must be connected to VCC_IO。
- Note:
  Reserve PAD for Update.
sheet 23
- tSD FLASH
- Note:
  Reserve PAD for Update.
sheet 24
- DVP Power
- FLASH LED Drive
- OPTION1
- OPTION2
- note：Drive up to total 1.5A or 0.75A per channel。
- note：Drive up to 500mA。
- OPTION3
- note：Drive up to 1.2A。
sheet 25
- MIPI Camera
sheet 26
- CIF Camera
sheet 27
- eDP Panel
- BACKLIGHT
